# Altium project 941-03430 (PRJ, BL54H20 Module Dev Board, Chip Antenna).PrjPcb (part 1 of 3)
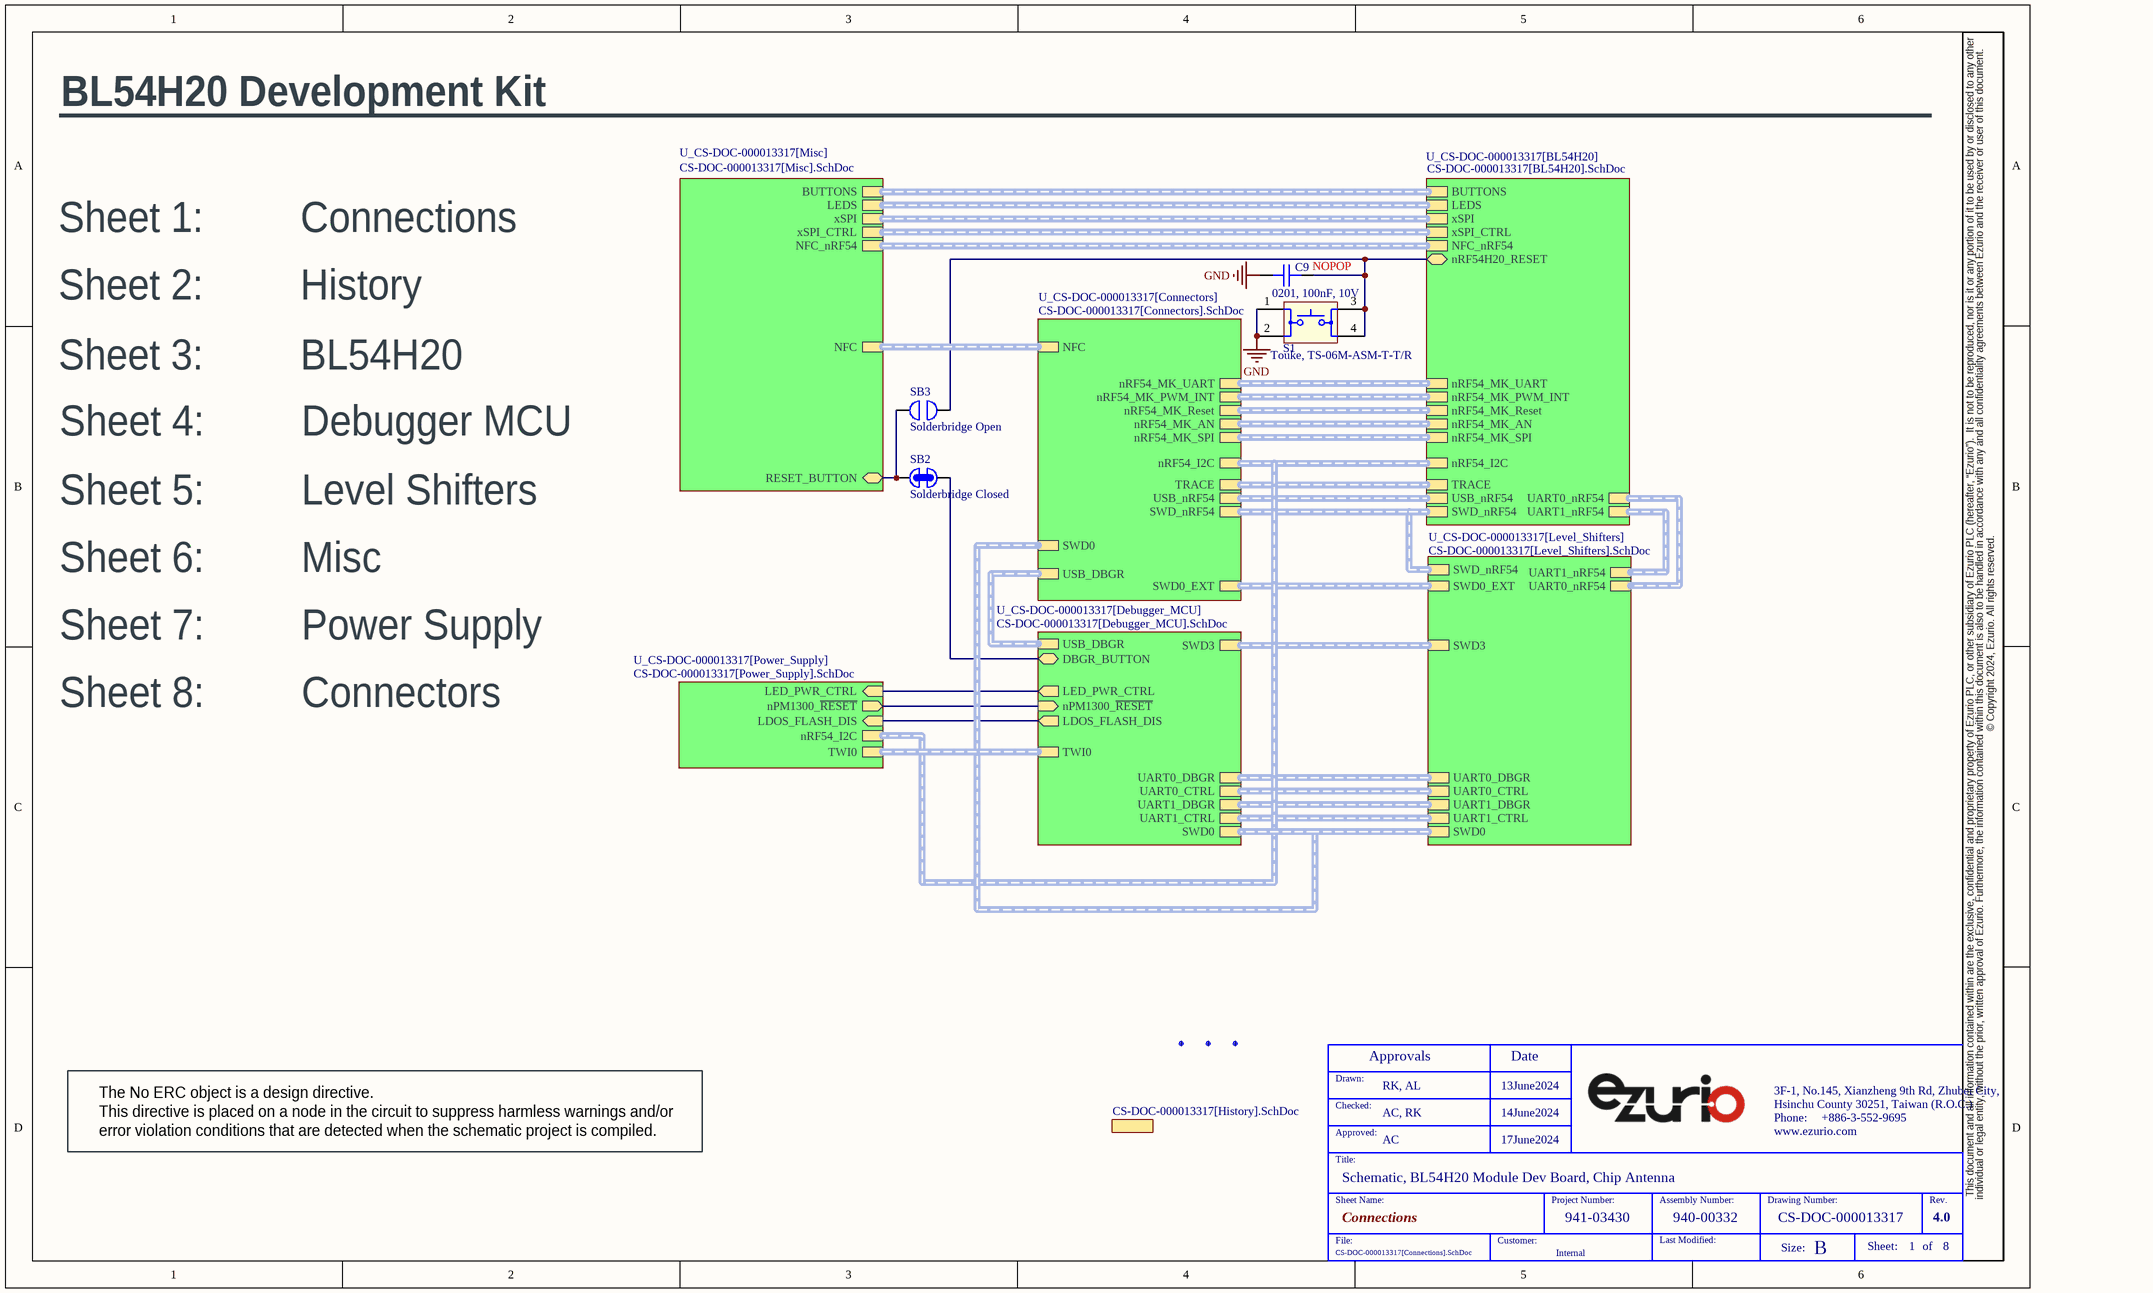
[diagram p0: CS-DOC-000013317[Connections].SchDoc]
ProjectWebsite: www.ezurio.com; ProjectVariantNumber: 940-00332; ProjectVariantDescription: Chip Antenna; ProjectTitle: BL54H20 Module Dev Board; ProjectSchematicRevision: 4.0; ProjectSchematicNumber: CS-DOC-000013317; ProjectRevision: 4.0; ProjectPhone: +886-3-552-9695; ProjectPCBRevision: 3.0; ProjectPCBNumber: 750-03430; ProjectNumber: 941-03430; ProjectDrawnDate: 13June2024; ProjectDrawnBy: RK, AL; ProjectCustomerName: Internal; ProjectCheckedDate: 14June2024; ProjectCheckedBy: AC, RK; ProjectBOMRevision: 4.0; ProjectBOMNumber: CS-DOC-000013318; ProjectAssyDocNumber: CS-DOC-000013316; ProjectApprovedDate: 17June2024; ProjectApprovedBy: AC; ProjectAddress3: Hsinchu County 30251, Taiwan (R.O.C.); ProjectAddress2: 3F-1, No.145, Xianzheng 9th Rd, Zhubei City,
8 sheets, 400 parts. Net scope: hierarchical (ports join the sheet entries above them; power ports are global).
Board file: 750-03430.PcbDoc
Sheets:
  CS-DOC-000013317[Connections].SchDoc
    CS-DOC-000013317[History] = CS-DOC-000013317[History].SchDoc
    U_CS-DOC-000013317[Connectors] = CS-DOC-000013317[Connectors].SchDoc
    U_CS-DOC-000013317[BL54H20] = CS-DOC-000013317[BL54H20].SchDoc
    U_CS-DOC-000013317[Debugger_MCU] = CS-DOC-000013317[Debugger_MCU].SchDoc
    U_CS-DOC-000013317[Level_Shifters] = CS-DOC-000013317[Level_Shifters].SchDoc
    U_CS-DOC-000013317[Misc] = CS-DOC-000013317[Misc].SchDoc
    U_CS-DOC-000013317[Power_Supply] = CS-DOC-000013317[Power_Supply].SchDoc

## Sheet CS-DOC-000013317[Connections].SchDoc: =BoardTitle +' Connections'
size B; Organization: Nordic Semiconductor; DocumentNumber: 1; SheetNumber: 1; SheetTotal: 8; CompanyName: Nordic Semiconductor; DocumentSize: A4; SheetName: Connections

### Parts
C9  0201, 100nF, 10V  [Cap, C0201, Height 0.3mm]
Fid1  Fiducial  [Fiducial]  (value not drawn)  (no BOM)
Fid2  Fiducial  [Fiducial]  (value not drawn)  (no BOM)
Fid3  Fiducial  [Fiducial]  (value not drawn)  (no BOM)
S1  Touke, TS-06M-ASM-T-T/R  [Touke, TS-06M-ASM-T]
SB2  Solderbridge Closed  [Solder Bridge Closed]  (net tie, no BOM)
SB3  Solderbridge Open  [Solder Bridge Open]  (no BOM)

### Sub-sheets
CS-DOC-000013317[History] = CS-DOC-000013317[History].SchDoc: no entries
U_CS-DOC-000013317[BL54H20] = CS-DOC-000013317[BL54H20].SchDoc: SWD_nRF54 (harness SWD), BUTTONS (harness UI), LEDS (harness UI), TRACE (harness TRACE), USB_nRF54 (harness USB_nRF), nRF54_I2C (harness I2C), nRF54_MK_UART (harness MIKROE UART), nRF54_MK_PWM_INT (harness MIKROE PWM INT), nRF54_MK_Reset (harness MIKROE Reset), nRF54_MK_AN (harness MIKROE Analog), nRF54_MK_SPI (harness MIKROE SPI), nRF54H20_RESET (bidir), xSPI (harness xSPI), NFC_nRF54 (harness NFC), UART0_nRF54 (harness UART), UART1_nRF54 (harness UART), xSPI_CTRL (harness xSPI_CTRL)
U_CS-DOC-000013317[Connectors] = CS-DOC-000013317[Connectors].SchDoc: SWD_nRF54 (harness SWD), TRACE (harness TRACE), NFC (harness NFC), SWD0_EXT (harness SWD), USB_nRF54 (harness USB_nRF), USB_DBGR (harness USB), nRF54_I2C (harness I2C), nRF54_MK_UART (harness MIKROE UART), nRF54_MK_PWM_INT (harness MIKROE PWM_INT), nRF54_MK_SPI (harness MIKROE SPI), nRF54_MK_AN (harness MIKROE Analog), nRF54_MK_Reset (harness MIKROE Reset), SWD0 (harness SWD)
U_CS-DOC-000013317[Debugger_MCU] = CS-DOC-000013317[Debugger_MCU].SchDoc: DBGR_BUTTON (bidir), SWD0 (harness SWD), UART0_DBGR (harness UART), USB_DBGR (harness USB), LED_PWR_CTRL (out), TWI0 (harness TWI), UART1_DBGR (harness UART), UART0_CTRL (harness UART CTRL), UART1_CTRL (harness UART CTRL), SWD3 (harness SWD), nPM1300_~{RESET} (in), LDOS_FLASH_DIS (out)
U_CS-DOC-000013317[Level_Shifters] = CS-DOC-000013317[Level_Shifters].SchDoc: SWD0 (harness SWD), UART0_DBGR (harness UART), SWD0_EXT (harness SWD), UART0_nRF54 (harness UART), UART1_nRF54 (harness UART), UART1_DBGR (harness UART), SWD_nRF54 (harness SWD), SWD3 (harness SWD), UART0_CTRL (harness UART CTRL), UART1_CTRL (harness UART CTRL)
U_CS-DOC-000013317[Misc] = CS-DOC-000013317[Misc].SchDoc: NFC_nRF54 (harness NFC), NFC (harness NFC), LEDS (harness UI), RESET_BUTTON (bidir), BUTTONS (harness UI), xSPI (harness xSPI), xSPI_CTRL (harness xSPI_CTRL)
U_CS-DOC-000013317[Power_Supply] = CS-DOC-000013317[Power_Supply].SchDoc: nRF54_I2C (harness I2C), LDOS_FLASH_DIS (in), nPM1300_~{RESET} (out), LED_PWR_CTRL (in), TWI0 (harness TWI)

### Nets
GND: C9.2 S1.1 S1.2
DBGR_BUTTON: SB2.2 ; sheet U_CS-DOC-000013317[Debugger_MCU]/DBGR_BUTTON
LDOS_FLASH_DIS: sheet U_CS-DOC-000013317[Debugger_MCU]/LDOS_FLASH_DIS, sheet U_CS-DOC-000013317[Power_Supply]/LDOS_FLASH_DIS
LED_PWR_CTRL: sheet U_CS-DOC-000013317[Debugger_MCU]/LED_PWR_CTRL, sheet U_CS-DOC-000013317[Power_Supply]/LED_PWR_CTRL
nPM1300_~{RESET}: sheet U_CS-DOC-000013317[Debugger_MCU]/nPM1300_~{RESET}, sheet U_CS-DOC-000013317[Power_Supply]/nPM1300_~{RESET}
nRF54H20_RESET: C9.1 S1.3 S1.4 SB3.2 ; sheet U_CS-DOC-000013317[BL54H20]/nRF54H20_RESET
RESET_BUTTON: SB2.1 SB3.1 ; sheet U_CS-DOC-000013317[Misc]/RESET_BUTTON

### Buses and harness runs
harness sheet U_CS-DOC-000013317[BL54H20]/BUTTONS = sheet U_CS-DOC-000013317[Misc]/BUTTONS
harness sheet U_CS-DOC-000013317[BL54H20]/LEDS = sheet U_CS-DOC-000013317[Misc]/LEDS
harness sheet U_CS-DOC-000013317[BL54H20]/NFC_nRF54 = sheet U_CS-DOC-000013317[Misc]/NFC_nRF54
harness sheet U_CS-DOC-000013317[BL54H20]/nRF54_I2C = sheet U_CS-DOC-000013317[Connectors]/nRF54_I2C = sheet U_CS-DOC-000013317[Power_Supply]/nRF54_I2C
harness sheet U_CS-DOC-000013317[BL54H20]/nRF54_MK_AN = sheet U_CS-DOC-000013317[Connectors]/nRF54_MK_AN
harness sheet U_CS-DOC-000013317[BL54H20]/nRF54_MK_PWM_INT = sheet U_CS-DOC-000013317[Connectors]/nRF54_MK_PWM_INT
harness sheet U_CS-DOC-000013317[BL54H20]/nRF54_MK_Reset = sheet U_CS-DOC-000013317[Connectors]/nRF54_MK_Reset
harness sheet U_CS-DOC-000013317[BL54H20]/nRF54_MK_SPI = sheet U_CS-DOC-000013317[Connectors]/nRF54_MK_SPI
harness sheet U_CS-DOC-000013317[BL54H20]/nRF54_MK_UART = sheet U_CS-DOC-000013317[Connectors]/nRF54_MK_UART
harness sheet U_CS-DOC-000013317[BL54H20]/SWD_nRF54 = sheet U_CS-DOC-000013317[Connectors]/SWD_nRF54 = sheet U_CS-DOC-000013317[Level_Shifters]/SWD_nRF54
harness sheet U_CS-DOC-000013317[BL54H20]/TRACE = sheet U_CS-DOC-000013317[Connectors]/TRACE
harness sheet U_CS-DOC-000013317[BL54H20]/UART0_nRF54 = sheet U_CS-DOC-000013317[Level_Shifters]/UART0_nRF54
harness sheet U_CS-DOC-000013317[BL54H20]/UART1_nRF54 = sheet U_CS-DOC-000013317[Level_Shifters]/UART1_nRF54
harness sheet U_CS-DOC-000013317[BL54H20]/USB_nRF54 = sheet U_CS-DOC-000013317[Connectors]/USB_nRF54
harness sheet U_CS-DOC-000013317[BL54H20]/xSPI = sheet U_CS-DOC-000013317[Misc]/xSPI
harness sheet U_CS-DOC-000013317[BL54H20]/xSPI_CTRL = sheet U_CS-DOC-000013317[Misc]/xSPI_CTRL
harness sheet U_CS-DOC-000013317[Connectors]/NFC = sheet U_CS-DOC-000013317[Misc]/NFC
harness sheet U_CS-DOC-000013317[Connectors]/SWD0 = sheet U_CS-DOC-000013317[Debugger_MCU]/SWD0 = sheet U_CS-DOC-000013317[Level_Shifters]/SWD0
harness sheet U_CS-DOC-000013317[Connectors]/SWD0_EXT = sheet U_CS-DOC-000013317[Level_Shifters]/SWD0_EXT
harness sheet U_CS-DOC-000013317[Connectors]/USB_DBGR = sheet U_CS-DOC-000013317[Debugger_MCU]/USB_DBGR
harness sheet U_CS-DOC-000013317[Debugger_MCU]/SWD3 = sheet U_CS-DOC-000013317[Level_Shifters]/SWD3
harness sheet U_CS-DOC-000013317[Debugger_MCU]/TWI0 = sheet U_CS-DOC-000013317[Power_Supply]/TWI0
harness sheet U_CS-DOC-000013317[Debugger_MCU]/UART0_CTRL = sheet U_CS-DOC-000013317[Level_Shifters]/UART0_CTRL
harness sheet U_CS-DOC-000013317[Debugger_MCU]/UART0_DBGR = sheet U_CS-DOC-000013317[Level_Shifters]/UART0_DBGR
harness sheet U_CS-DOC-000013317[Debugger_MCU]/UART1_CTRL = sheet U_CS-DOC-000013317[Level_Shifters]/UART1_CTRL
harness sheet U_CS-DOC-000013317[Debugger_MCU]/UART1_DBGR = sheet U_CS-DOC-000013317[Level_Shifters]/UART1_DBGR

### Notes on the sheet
- ________________________________________________________________
- BL54H20 Development Kit
- Sheet 1:         Connections
- (near C9) NOPOP
- Sheet 2:         History
- Sheet 3:         BL54H20
- Sheet 4:         Debugger MCU
- Sheet 5:         Level Shifters
- Sheet 6:         Misc
- Sheet 7:         Power Supply
- Sheet 8:         Connectors
- The No ERC object is a design directive.
  This directive is placed on a node in the circuit to suppress harmless warnings and/or error violation conditions that are detected when the schematic project is compiled.

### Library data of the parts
C9 = CMP-CAP-502-00106-1.11: CAP, SMT, 0201, MLCC, 100nF, 10V, X7S, 10%; Manufacturer: Murata; Manufacturer Part Number: GRM033C71A104KE14#; Substitutes Allowed: NO
Fid1-Fid3 = CMP-MSC-SMT-WTS-522-0002-1.8: Fiducial Mark; Substitutes Allowed: NO
S1 = CMP-SW-516-00005-1.12: SW, SMT, Tact, Vertical, Momentary On, 6mm x 6mm x 4.3mm; Substitutes Allowed: NO; Voltage Rating AC/DC: 500VAC-1 minute; Switch Circuit: SPST; Switch Function: (On, Off, Mom)
SB2 = CMP-Misc-522-00004-1.17: MSC, Solderbridge Closed
SB3 = CMP-Misc-522-00003-1.9: MSC, Solderbridge Open

## Sheet CS-DOC-000013317[History].SchDoc
size B; SheetNumber: 2; SheetTotal: 8; SheetName: History
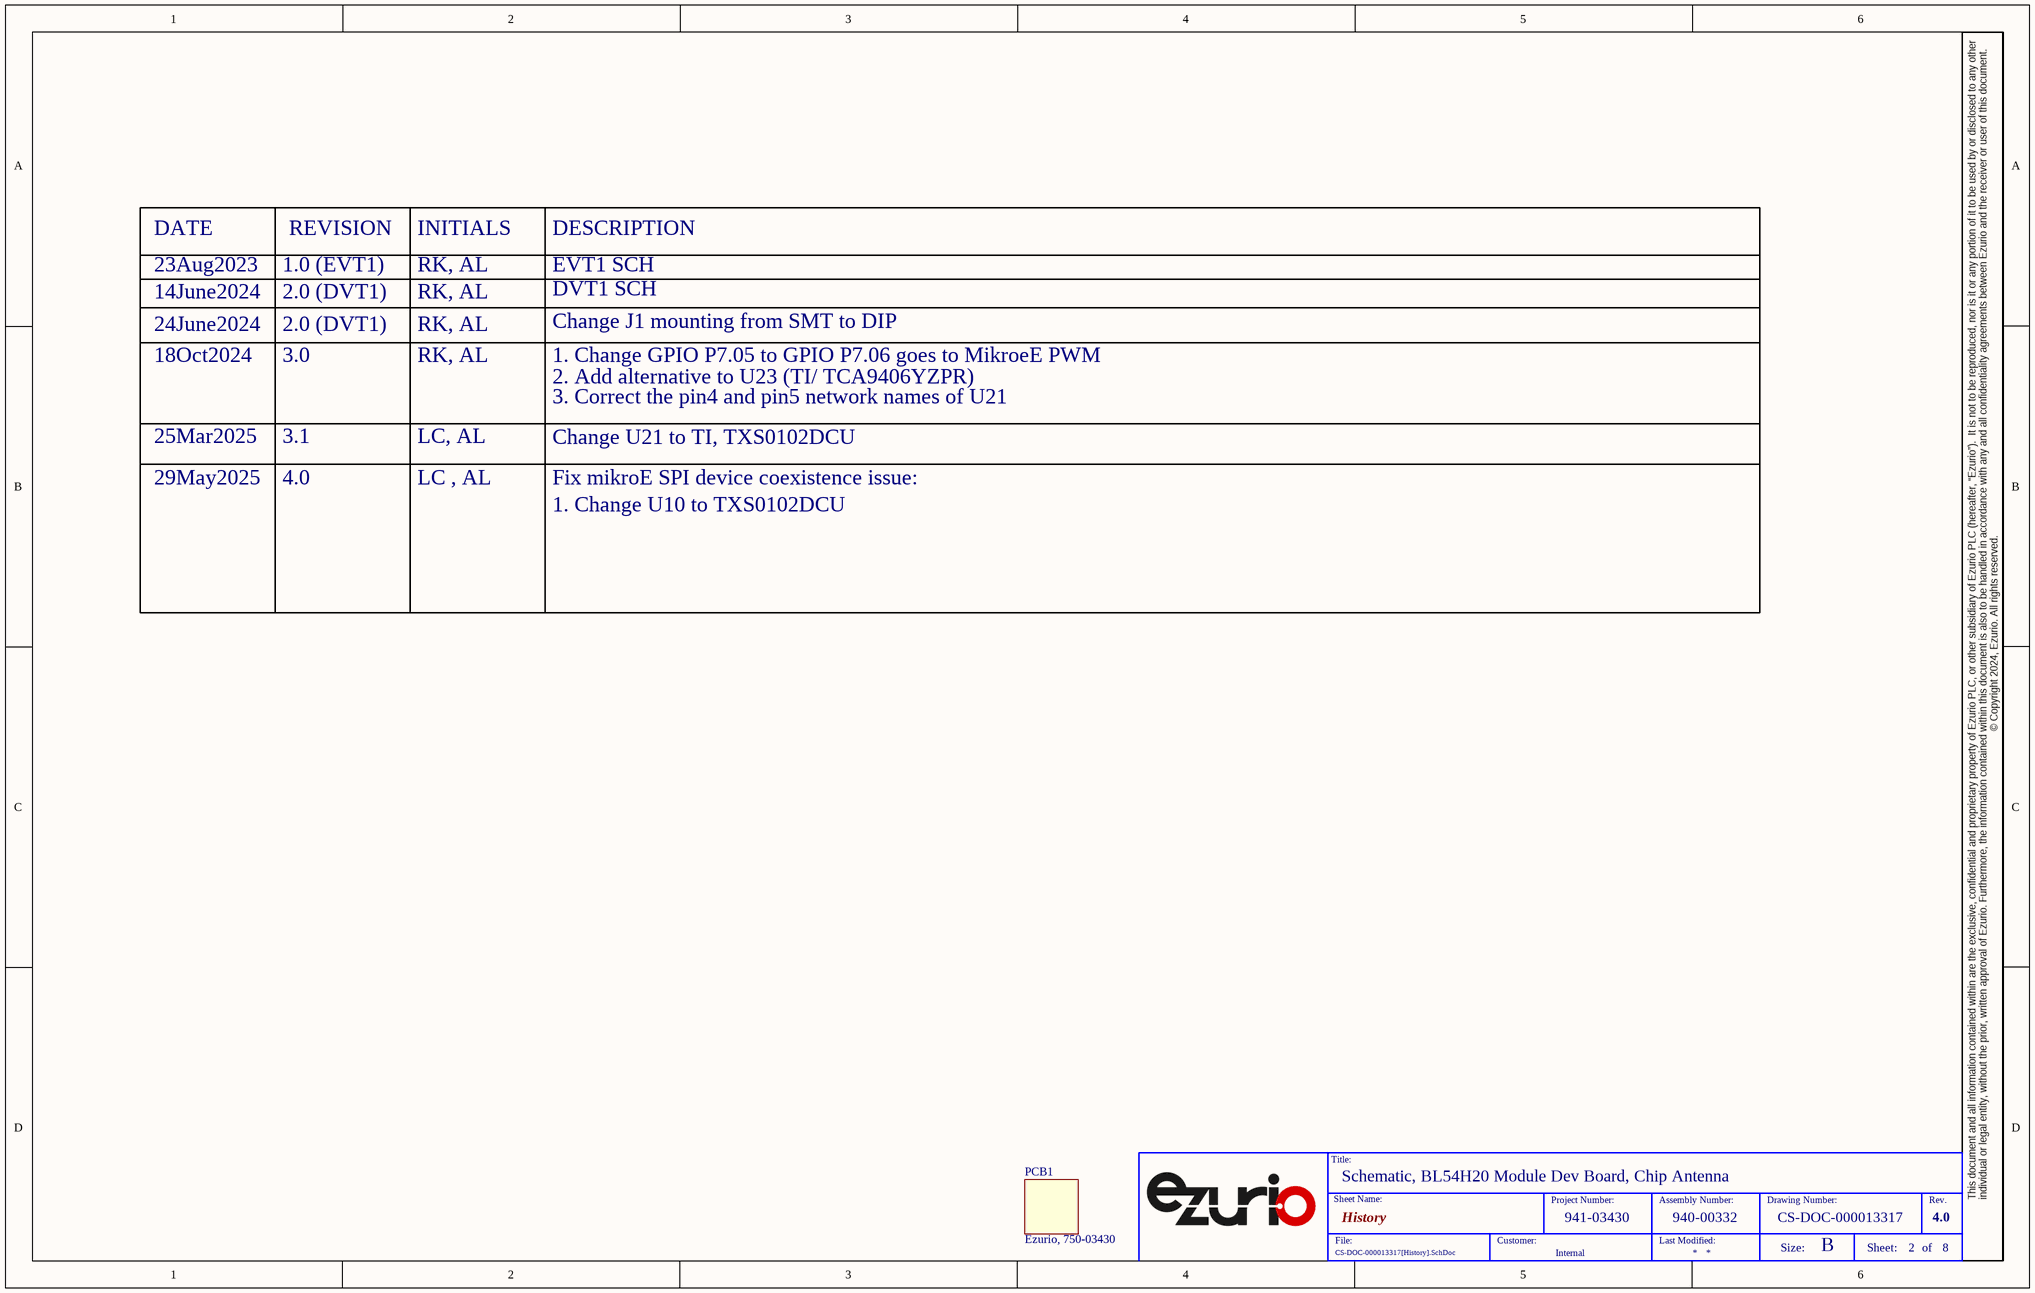
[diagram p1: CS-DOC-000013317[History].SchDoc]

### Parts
PCB1  Ezurio, 750-03430  [Laird, Logo, Silkscreen, TW]  (mechanical)

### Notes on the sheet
- DATE
- REVISION
- INITIALS
- DESCRIPTION
- 23Aug2023
- 14June2024
- 1.0 (EVT1)
- 2.0 (DVT1)
- RK, AL
- EVT1 SCH
- DVT1 SCH
- 24June2024
- 18Oct2024
- 3.0
- Change J1 mounting from SMT to DIP
- 1. Change GPIO P7.05 to GPIO P7.06 goes to MikroeE PWM
- 2. Add alternative to U23 (TI/ TCA9406YZPR)
- 3. Correct the pin4 and pin5 network names of U21
- 25Mar2025
- 29May2025
- 3.1
- 4.0
- LC, AL
- LC , AL
- Change U21 to TI, TXS0102DCU
- Fix mikroE SPI device coexistence issue:
- 1. Change U10 to TXS0102DCU

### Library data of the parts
PCB1 = CMP-PCB-750-00054-1.1: PCB, BL54H20 Module Dev Board, Chip Antenna; Substitutes Allowed: NO

## Sheet CS-DOC-000013317[Connectors].SchDoc: =BoardTitle +' Connectors'
size OrCAD C; Organization: Nordic Semiconductor; DocumentNumber: 8; SheetNumber: 8; SheetTotal: 8; CompanyName: Nordic Semiconductor; DocumentSize: A4; SheetName: Connectors
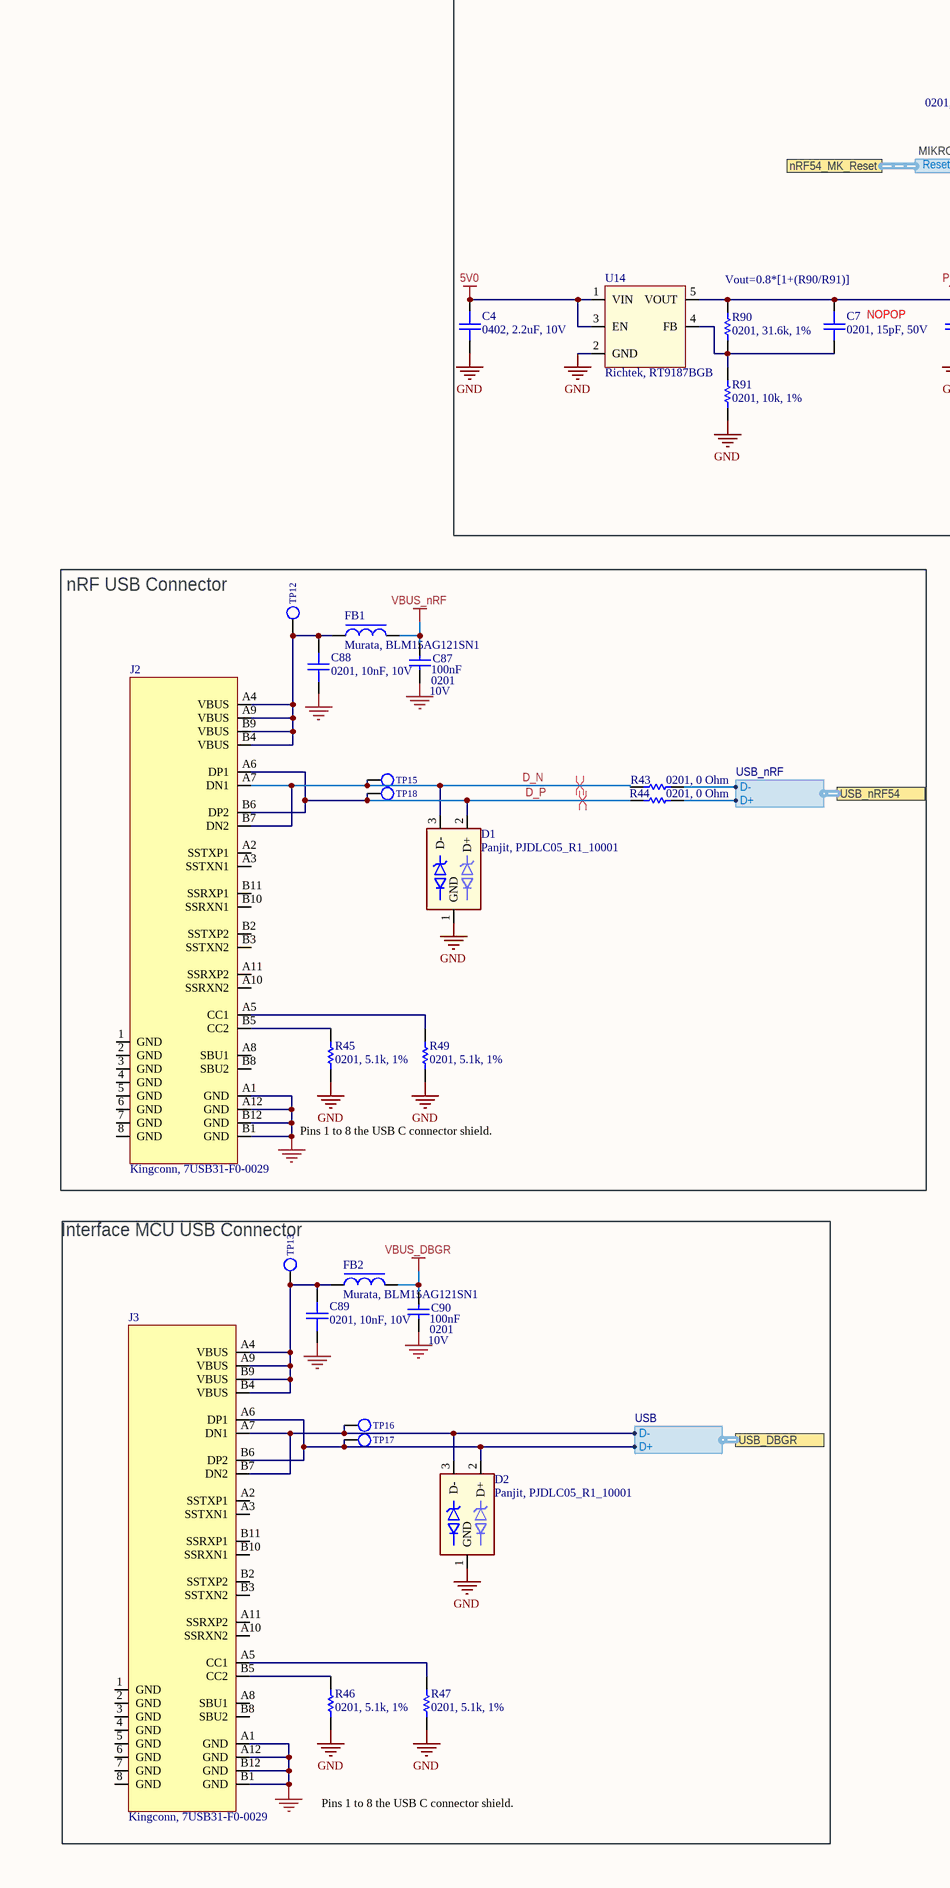
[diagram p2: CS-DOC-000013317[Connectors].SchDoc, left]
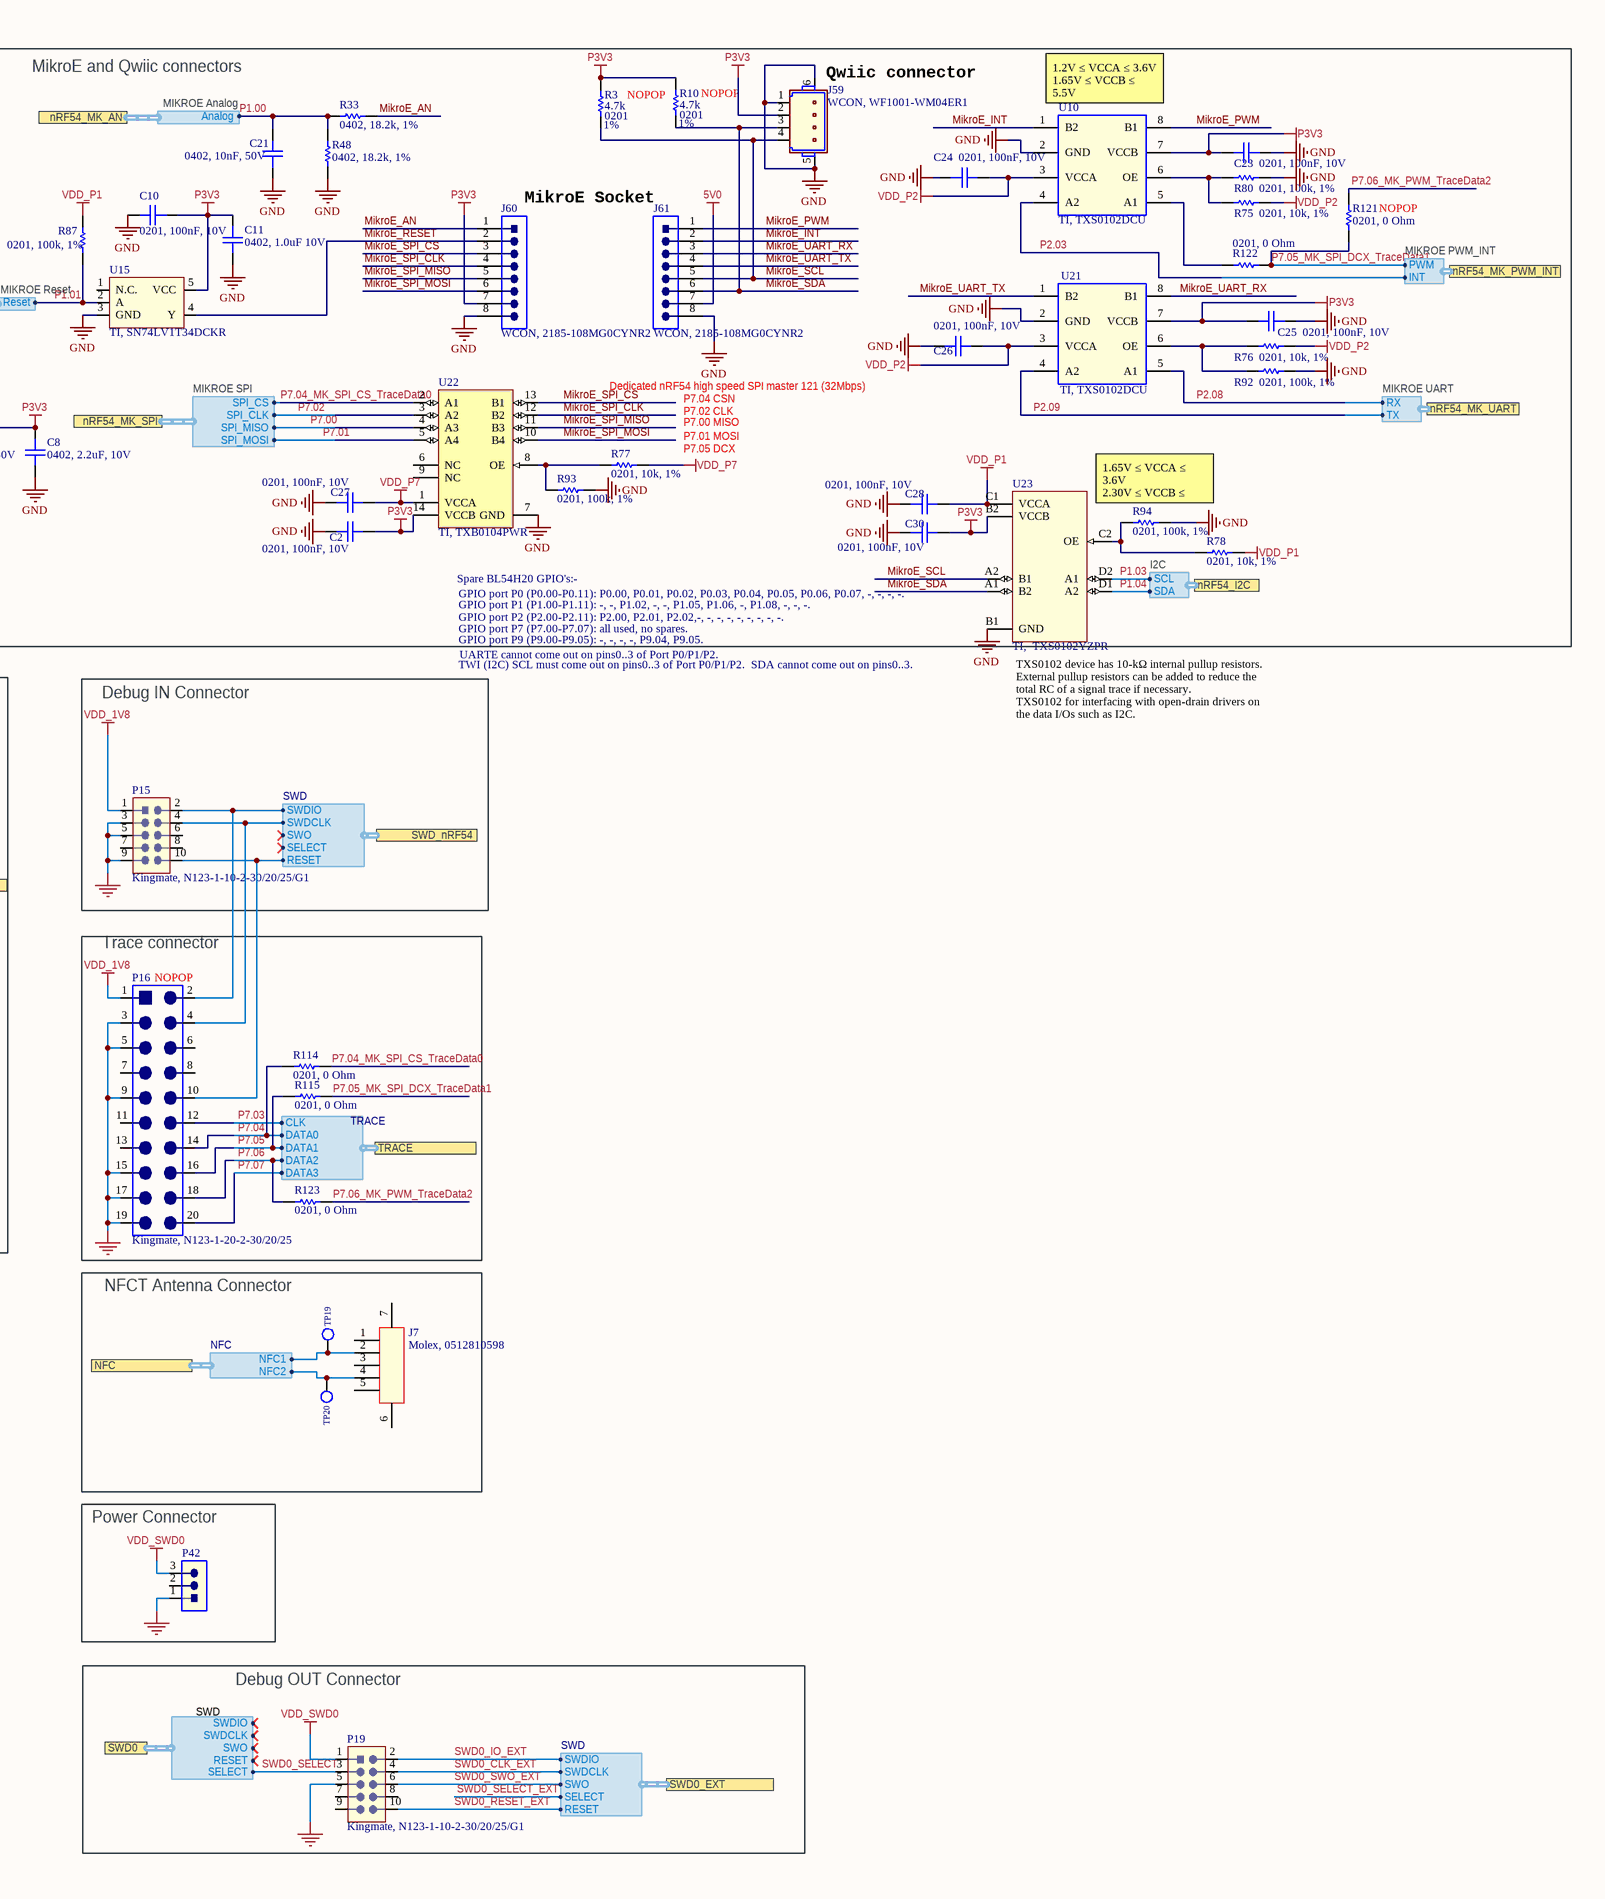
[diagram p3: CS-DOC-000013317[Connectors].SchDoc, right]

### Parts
C2  0201, 100nF, 10V  [Cap, C0201, Height 0.3mm]
C4  0402, 2.2uF, 10V  [Chip. 0402, RF]
C7  0201, 15pF, 50V  [Cap, C0201, Height 0.3mm]
C8  0402, 2.2uF, 10V  [Chip. 0402, RF]
C10  0201, 100nF, 10V  [Cap, C0201, Height 0.3mm]
C11  0402, 1.0uF 10V  [Chip. 0402, RF]
C21  0402, 10nF, 50V  [Chip. 0402, RF]
C23  0201, 100nF, 10V  [Cap, C0201, Height 0.3mm]
C24  0201, 100nF, 10V  [Cap, C0201, Height 0.3mm]
C25  0201, 100nF, 10V  [Cap, C0201, Height 0.3mm]
C26  0201, 100nF, 10V  [Cap, C0201, Height 0.3mm]
C27  0201, 100nF, 10V  [Cap, C0201, Height 0.3mm]
C28  0201, 100nF, 10V  [Cap, C0201, Height 0.3mm]
C30  0201, 100nF, 10V  [Cap, C0201, Height 0.3mm]
C87  value 100nF  Footprint: 0201  Voltage: 10V  [Cap, C0201, Height 0.3mm]  (hidden comment: 0201, 100nF, 10V)
C88  0201, 10nF, 10V  [Cap, C0201, Height 0.3mm]
C89  0201, 10nF, 10V  [Cap, C0201, Height 0.3mm]
C90  value 100nF  Footprint: 0201  Voltage: 10V  [Cap, C0201, Height 0.3mm]  (hidden comment: 0201, 100nF, 10V)
D1  Panjit, PJDLC05_R1_10001  [SOT-23]
D2  Panjit, PJDLC05_R1_10001  [SOT-23]
FB1  Murata, BLM15AG121SN1  [FB, FB0402, RF]
FB2  Murata, BLM15AG121SN1  [FB, FB0402, RF]
J2  Kingconn, 7USB31-F0-0029  [Kingconn, 7USB31-F0-0029]
J3  Kingconn, 7USB31-F0-0029  [Kingconn, 7USB31-F0-0029]
J7  Molex, 0512810598  [Molex, 0512810598]
J59  WCON, WF1001-WM04ER1  [CON WAFER, 1X4P]
J60  WCON, 2185-108MG0CYNR2  [2P54MM-1X8, Female]
J61  WCON, 2185-108MG0CYNR2  [2P54MM-1X8, Female]
P15  Kingmate, N123-1-10-2-30/20/25/G1  [1P27MM-2X5 Male]
P16  Kingmate, N123-1-20-2-30/20/25  [1P27MM-2X10 Male]
P19  Kingmate, N123-1-10-2-30/20/25/G1  [1P27MM-2X5 Male]
P42  Kingmate, S113-A-03-2-60/33-F0  [2P54MM-1X3, male]  (value not drawn)
R3  value 4.7k  Tolerance: 1%  Footprint: 0201  [RES, R0201, Height 0.23mm]  (hidden comment: 0201, 4.7k, 1%)
R10  value 4.7k  Tolerance: 1%  Footprint: 0201  [RES, R0201, Height 0.23mm]  (hidden comment: 0201, 4.7k, 1%)
R33  0402, 18.2k, 1%  [RES, R0402, RF]
R43  0201, 0 Ohm  [RES, R0201, Height 0.23mm]
R44  0201, 0 Ohm  [RES, R0201, Height 0.23mm]
R45  0201, 5.1k, 1%  [RES, R0201, Height 0.23mm]
R46  0201, 5.1k, 1%  [RES, R0201, Height 0.23mm]
R47  0201, 5.1k, 1%  [RES, R0201, Height 0.23mm]
R48  0402, 18.2k, 1%  [RES, R0402, RF]
R49  0201, 5.1k, 1%  [RES, R0201, Height 0.23mm]
R75  0201, 10k, 1%  [RES, R0201, Height 0.23mm]
R76  0201, 10k, 1%  [RES, R0201, Height 0.23mm]
R77  0201, 10k, 1%  [RES, R0201, Height 0.23mm]
R78  0201, 10k, 1%  [RES, R0201, Height 0.23mm]
R80  0201, 100k, 1%  [RES, R0201, Height 0.23mm]
R87  0201, 100k, 1%  [RES, R0201, Height 0.23mm]
R90  0201, 31.6k, 1%  [RES, R0201, Height 0.23mm]
R91  0201, 10k, 1%  [RES, R0201, Height 0.23mm]
R92  0201, 100k, 1%  [RES, R0201, Height 0.23mm]
R93  0201, 100k, 1%  [RES, R0201, Height 0.23mm]
R94  0201, 100k, 1%  [RES, R0201, Height 0.23mm]
R114  0201, 0 Ohm  [RES, R0201, Height 0.23mm]
R115  0201, 0 Ohm  [RES, R0201, Height 0.23mm]
R121  0201, 0 Ohm  [RES, R0201, Height 0.23mm]
R122  0201, 0 Ohm  [RES, R0201, Height 0.23mm]
R123  0201, 0 Ohm  [RES, R0201, Height 0.23mm]
TP12  SMT, 1.5mm, Test Pad  [Test Point, SMT 1.5mm Round]  (value not drawn)  (no BOM)
TP13  SMT, 1.5mm, Test Pad  [Test Point, SMT 1.5mm Round]  (value not drawn)  (no BOM)
TP15  SMT, 1.5mm, Test Pad  [Test Point, SMT 1.5mm Round]  (value not drawn)  (no BOM)
TP16  SMT, 1.5mm, Test Pad  [Test Point, SMT 1.5mm Round]  (value not drawn)  (no BOM)
TP17  SMT, 1.5mm, Test Pad  [Test Point, SMT 1.5mm Round]  (value not drawn)  (no BOM)
TP18  SMT, 1.5mm, Test Pad  [Test Point, SMT 1.5mm Round]  (value not drawn)  (no BOM)
TP19  SMT, 1.5mm, Test Pad  [Test Point, SMT 1.5mm Round]  (value not drawn)  (no BOM)
TP20  SMT, 1.5mm, Test Pad  [Test Point, SMT 1.5mm Round]  (value not drawn)  (no BOM)
U10  TI, TXS0102DCU  [VFSOP8_2x2.3]
U14  Richtek, RT9187BGB  [SOT23-5, Height1.3mm]
U15  TI, SN74LV1T34DCKR  [SC70-5]
U21  TI, TXS0102DCU  [VFSOP8_2x2.3]
U22  TI, TXB0104PWR  [SOP-14, Body 5.1x4.5mm, Pitch 0.65mm, IPC High Density]
U23  TI,  TXS0102YZPR  [TI, TXS0102YZPR]

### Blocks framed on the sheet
MikroE and Qwiic connectors: C2 C4 C7 C8 C10 C11 C21 C23-C28 C30 J59-J61 R3 R10 R33 R48 R75-R78 R80 R87 R90-R94 R121 R122 U10 U14 U15 U21-U23
nRF USB Connector: C87 C88 D1 FB1 J2 R43-R45 R49 TP12 TP15 TP18
Debug IN Connector: P15
Trace connector: P16 R114 R115 R123
Interface MCU USB Connector: C89 C90 D2 FB2 J3 R46 R47 TP13 TP16 TP17
NFCT Antenna Connector: J7 TP19 TP20
Power Connector: P42
Debug OUT Connector: P19

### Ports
NFC (harness NFC), nRF54_I2C (harness I2C), nRF54_MK_AN (harness MIKROE Analog), nRF54_MK_PWM_INT (harness MIKROE PWM_INT), nRF54_MK_Reset (harness MIKROE Reset), nRF54_MK_SPI (harness MIKROE SPI), nRF54_MK_UART (harness MIKROE UART), SWD0 (harness SWD), SWD0_EXT (harness SWD), SWD_nRF54 (harness SWD), TRACE (harness TRACE), USB_DBGR (harness USB), USB_nRF54 (harness USB_nRF)

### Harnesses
USB_nRF: D+, D-
SWD: SWDIO, SWDCLK, SWO, RESET, SELECT
TRACE: CLK, DATA0, DATA1, DATA3, DATA2
NFC: NFC2, NFC1
I2C: SCL, SDA
MIKROE UART: TX, RX
MIKROE PWM_INT: PWM, INT
MIKROE SPI: SPI_MISO, SPI_MOSI, SPI_CLK, SPI_CS
MIKROE Analog: Analog
MIKROE Reset: Reset
USB: D+, D-

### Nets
5V0: C4.1 J61.7 U14.1(VIN) U14.3(EN)
GND: C2.1 C4.2 C8.2 C10.2 C11.2 C21.1 C23.1 C24.1 C25.1 C26.1 C27.1 C28.1 C30.1 C87.2 C88.1 C89.1 C90.2 D1.1(GND) D2.1(GND) J2.A1(GND) J2.A12(GND) J2.B1(GND) J2.B12(GND) J3.A1(GND) J3.A12(GND) J3.B1(GND) J3.B12(GND) J59.1 J59.5(GND) J59.6(GND2) J60.8 J61.8 P15.3 P15.5 P15.9 P16.3 P16.5 P16.9 P16.15 P16.17 P16.19 P19.5 P42.1 R45.1 R46.1 R47.2 R48.1 R49.1 R80.2 R91.2 R92.2 R93.2 R94.2 U10.2(GND) U14.2(GND) U15.3(GND) U21.2(GND) U22.7(GND) U23.B1(GND)
P3V3: C2.2 C7.1 C8.1 C10.1 C11.1 C23.2 C25.2 C30.2 J59.2 J60.7 R3.2 R10.2 R90.1 U10.7(VCCB) U14.5(VOUT) U15.5(VCC) U21.7(VCCB) U22.14(VCCB) U23.B2(VCCB)
VBUS_DBGR: C90.1 FB2.2
VBUS_nRF: C87.1 FB1.2
VDD_1V8: P15.1 P16.1
VDD_P1: C28.2 R78.2 R87.1 U23.C1(VCCA)
VDD_P2: C24.2 C26.2 R75.2 R76.2 U10.3(VCCA) U21.3(VCCA)
VDD_P7: C27.2 R77.2 U22.1(VCCA)
VDD_SWD0: P19.1 P42.3
D_N: D1.3(D-) J2.A7(DN1) J2.B7(DN2) R43.2 TP15.1
D_P: D1.2(D+) J2.A6(DP1) J2.B6(DP2) R44.2 TP18.1
DBGR_N: D2.3(D-) J3.A7(DN1) J3.B7(DN2) TP16.1 ; port USB_DBGR.D-
DBGR_P: D2.2(D+) J3.A6(DP1) J3.B6(DP2) TP17.1 ; port USB_DBGR.D+
MikroE_AN: J60.1 R33.2
MikroE_INT: J61.2 U10.1(B2)
MikroE_PWM: J61.1 U10.8(B1)
MikroE_RESET: J60.2 U15.4(Y)
MikroE_SCL: J59.4 J61.5 R3.1 U23.A2(B1)
MikroE_SDA: J59.3 J61.6 R10.1 U23.A1(B2)
MikroE_SPI_CLK: J60.4 U22.12(B2)
MikroE_SPI_CS: J60.3 U22.13(B1)
MikroE_SPI_MISO: J60.5 U22.11(B3)
MikroE_SPI_MOSI: J60.6 U22.10(B4)
MikroE_UART_RX: J61.3 U21.8(B1)
MikroE_UART_TX: J61.4 U21.1(B2)
NFC1: J7.2 TP19.1 ; port NFC.NFC1
NFC2: J7.4 TP20.1 ; port NFC.NFC2
nRF54_N: R43.1 ; port USB_nRF54.D-
nRF54_P: R44.1 ; port USB_nRF54.D+
nRF54H20_RESET: P15.10 P16.10 ; port SWD_nRF54.RESET
P1.00: C21.2 R33.1 R48.2 ; port nRF54_MK_AN.Analog
P1.01: R87.2 U15.2(A) ; port nRF54_MK_Reset.Reset
P1.03: U23.D2(A1) ; port nRF54_I2C.SCL
P1.04: U23.D1(A2) ; port nRF54_I2C.SDA
P2.03: U10.4(A2) ; port nRF54_MK_PWM_INT.INT
P2.08: U21.5(A1) ; port nRF54_MK_UART.RX
P2.09: U21.4(A2) ; port nRF54_MK_UART.TX
P7.00: U22.4(A3) ; port nRF54_MK_SPI.SPI_MISO
P7.01: U22.5(A4) ; port nRF54_MK_SPI.SPI_MOSI
P7.02: U22.3(A2) ; port nRF54_MK_SPI.SPI_CLK
P7.03: P16.12 ; port TRACE.CLK
P7.04: P16.14 R114.2 ; port TRACE.DATA0
P7.04_MK_SPI_CS_TraceData0: R114.1 U22.2(A1) ; port nRF54_MK_SPI.SPI_CS
P7.05: P16.16 R115.2 ; port TRACE.DATA1
P7.05_MK_SPI_DCX_TraceData1: R115.1 R121.2 R122.1 ; port nRF54_MK_PWM_INT.PWM
P7.06: P16.18 R123.2 ; port TRACE.DATA2
P7.06_MK_PWM_TraceData2: R121.1 R123.1
P7.07: P16.20 ; port TRACE.DATA3
SWD0_CLK_EXT: P19.4 ; port SWD0_EXT.SWDCLK
SWD0_IO_EXT: P19.2 ; port SWD0_EXT.SWDIO
SWD0_RESET_EXT: P19.10 ; port SWD0_EXT.RESET
SWD0_SELECT: P19.3 ; port SWD0.SELECT
SWD0_SWO_EXT: P19.6 ; port SWD0_EXT.SWO
SWDCLK: P15.4 P16.4 ; port SWD_nRF54.SWDCLK
SWDIO: P15.2 P16.2 ; port SWD_nRF54.SWDIO
NetC7_2: C7.2 R90.2 R91.1 U14.4(FB)
NetC88_2: C88.2 FB1.1 J2.A4(VBUS) J2.A9(VBUS) J2.B4(VBUS) J2.B9(VBUS) TP12.1
NetC89_2: C89.2 FB2.1 J3.A4(VBUS) J3.A9(VBUS) J3.B4(VBUS) J3.B9(VBUS) TP13.1
NetJ2_A5: J2.A5(CC1) R49.2
NetJ2_B5: J2.B5(CC2) R45.2
NetJ3_A5: J3.A5(CC1) R47.1
NetJ3_B5: J3.B5(CC2) R46.2
NetR75_1: R75.1 R80.1 U10.6(OE)
NetR76_1: R76.1 R92.1 U21.6(OE)
NetR77_1: R77.1 R93.1 U22.8(OE)
NetR78_1: R78.1 R94.1 U23.C2(OE)
NetR122_2: R122.2 U10.5(A1)

Not connected (* = marked no-connect by the designer): J2 1(GND) 2(GND) 3(GND) 4(GND) 5(GND) 6(GND) 7(GND) 8(GND) A2(SSTXP1) A3(SSTXN1) A8(SBU1) A10(SSRXN2) A11(SSRXP2) B2(SSTXP2) B3(SSTXN2) B8(SBU2) B10(SSRXN1) B11(SSRXP1); J3 1(GND) 2(GND) 3(GND) 4(GND) 5(GND) 6(GND) 7(GND) 8(GND) A2(SSTXP1) A3(SSTXN1) A8(SBU1) A10(SSRXN2) A11(SSRXP2) B2(SSTXP2) B3(SSTXN2) B8(SBU2) B10(SSRXN1) B11(SSRXP1); J7 1 3 5 6 7; P15 6 7 8; P16 6 7 8 11 13; P19 7 8 9; P42 2; U15 1(N.C.); U22 6(NC) 9(NC)

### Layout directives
differential pair; differential pair class USB_CONN; net class USB: D_N, D_P

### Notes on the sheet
- (near J59) Qwiic connector
- NOPOP
- (near R10) NOPOP
- (near U10) 1.2V ≤ VCCA ≤ 3.6V
  1.65V ≤ VCCB ≤ 5.5V
  & VCCA ≤VCCB
- MikroE Socket
- (near R121) NOPOP
- Dedicated nRF54 high speed SPI master 121 (32Mbps)
- Vout=0.8*[1+(R90/R91)]
- (near C7) NOPOP
- P7.00 MISO
- P7.01 MOSI
- P7.02 CLK
- P7.04 CSN
- (near R77) P7.05 DCX
- (near U23) 1.65V ≤ VCCA ≤ 3.6V
  2.30V ≤ VCCB ≤ 5.5V
  & VCCA ≤VCCB
- Spare BL54H20 GPIO's:-
- GPIO port P7 (P7.00-P7.07): all used, no spares.
- (near U23) GPIO port P0 (P0.00-P0.11): P0.00, P0.01, P0.02, P0.03, P0.04, P0.05, P0.06, P0.07, -, -, -, -.
- GPIO port P1 (P1.00-P1.11): -, -, P1.02, -, -, P1.05, P1.06, -, P1.08, -, -, -.
- GPIO port P2 (P2.00-P2.11): P2.00, P2.01, P2.02,-, -, -, -, -, -, -, -, -.
- GPIO port P9 (P9.00-P9.05): -, -, -, -, P9.04, P9.05.
- TWI (I2C) SCL must come out on pins0..3 of Port P0/P1/P2.  SDA cannot come out on pins0..3.
- UARTE cannot come out on pins0..3 of Port P0/P1/P2.
- (near U23) TXS0102 device has 10-kΩ internal pullup resistors. External pullup resistors can be added to reduce the total RC of a signal trace if necessary.
  TXS0102 for interfacing with open-drain drivers on the data I/Os such as I2C.
- (near P16) NOPOP
- Pins 1 to 8 the USB C connector shield.

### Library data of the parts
C2 C10 C23-C28 C30 = CMP-CAP-502-00106-1.11: as C9 on sheet CS-DOC-000013317[Connections]
C4 C8 = CMP-CAP-502-00198-1.11: CAP, SMT, 0402, MLCC, 2.2uF, 10V, X7S, 10%; Manufacturer: Murata; Manufacturer Part Number: GRM155C71A225KE11#; Substitutes Allowed: NO
C7 = CMP-CAP-502-00072-1.19: CAP, SMT, 0201, MLCC, 15pF, 50V, C0G, 5%; Manufacturer Part Number: CC0201JRNPO9BN150; Alt. Manufacturer: MURATA; Manufacturer: Yageo; Alt. Manufacturer Part Number: GRM0335C1H150JA01#; Substitutes Allowed: YES
C11 = CMP-CAP-502-00101-1.17: CAP, SMT, 0402, MLCC, 1.0uF, 10V, X7S, 10%; Manufacturer: Murata; Manufacturer Part Number: GRM155C71A105KE11#; Substitutes Allowed: NO
C21 = CMP-CAP-502-00063-1.16: CAP, SMT, 0402, MLCC, 10nF, 50V, X7R, 10%; Manufacturer Part Number: CC0402KRX7R9BB103; Manufacturer: Yageo; Substitutes Allowed: NO
C87 C90 = CMP-CAP-502-00106-1.11: CAP, SMT, 0201, MLCC, 100nF, 10V, X7S, 10%; Manufacturer Part Number: GRM033C71A104KE14#; Manufacturer: Murata; Substitutes Allowed: NO
C88 C89 = CMP-CAP-502-00031-1.14: CAP, SMT, 0201, MLCC, 10nF, 10V, X7R, 10%; Manufacturer: Walsin; Alt. Manufacturer: Murata; Manufacturer Part Number: 0201B103K100CT; Alt. Manufacturer Part Number: GRM033R71A103K; Substitutes Allowed: YES
D1 D2 = CMP-IC-510-00074-1.2: IC, SMT, SOT23, Overvoltage-Suppressor,5V,400W,ESD-15KV-Air, 8KV-Contact, 3.3V~24V, 400W; Substitutes Allowed: NO
FB1 FB2 = CMP-FB-505-00005-1.3: FB, SMT, 0402, 120 Ohm @ 100MHz, 450mA, 190 mOhm,; Substitutes Allowed: NO; Current: 550mA
J2 J3 = CMP-CON-130-00120-1.4: CON, TH, USB-C Type, 24 PIN, DIP+SMT 90d; Substitutes Allowed: NO; Rows: NA; Pin Pitch: 0.5mm
J7 = CMP-CON-130-00213-1.1: CON, SMT,Custom, FPC,1x5,1.20mm, NFC Connector; Subpart Type: FFC; Pin Pitch: 0.5mm; Rows: 1; Substitutes Allowed: NO
J59 = CMP-CON-130-00167-1.4: CON, SMT, Wafer, 1x4, Pitch 1.0mm, Vertical; Subpart Type: WIRE TO BOARD WAFER; Substitutes Allowed: NO; Rows: 1; Voltage: 100V
J60 J61 = CMP-CON-130-00168-1.2: CON, SMT, Female Header, 2P54MM-1X8, Pitch 2.54mm, PHY 0.64mm; Alt. Manufacturer: Kingmate; Alt. Manufacturer Part Number: S214-B-08-2-89-F1; Substitutes Allowed: YES; Rows: 1
P15 P19 = CMP-CON-130-00112-1.1: CON, SMT, Header, 2x5, Pitch 1.27mm, Vertical; Rows: 2; Substitutes Allowed: NO
P16 = CMP-CON-130-00048-1.7: CON, SMT, Header, 2x10 pin, 1.27mm pitch, Male,; Voltage: 1000V; Substitutes Allowed: NO; Rows: 2
P42 = CMP-CON-130-00220-1.3: CON, SMT, Header, 1X3 pins, 2.54mm pitch, Male, Vertical; Rows: 1; Substitutes Allowed: NO
R3 R10 = CMP-RES-514-00018-1.29: RES, SMT, 0201, Thick Film, 4.7k, 1%, 0.05W; Manufacturer: Yageo; Alt. Manufacturer: Any; Manufacturer Part Number: RC0201FR-074K7L; Substitutes Allowed: YES
R33 R48 = CMP-RES-514-00333-1.2: RES, SMT, 0402, Thick Film, 18.2k, 1%, 0.0625W; Alt. Manufacturer Part Number: Any; Manufacturer Part Number: RC0402FR-0718K2L; Manufacturer: Yageo; Substitutes Allowed: YES
R43 R44 = CMP-RES-514-00004-1.31: RES, SMT, 0201, Thick Film, 0, 0.05W; Manufacturer: Yageo; Alt. Manufacturer: Any; Manufacturer Part Number: RC0201JR-070RL; Tolerance: NA; Substitutes Allowed: YES; Value: 0
R45-R47 R49 = CMP-RES-514-00342-1.0: RES, SMT, 0201, Thick Film, 5.1k, 1%, 0.05W; Manufacturer: Yageo; Alt. Manufacturer Part Number: Any; Manufacturer Part Number: RC0201FR-075K1L; Substitutes Allowed: YES
R75-R78 R91 = CMP-RES-514-00247-1.2: RES, SMT, 0201, Thick Film, 10k, 1%, 0.05W; Alt. Manufacturer Part Number: Any; Manufacturer Part Number: RC0201FR-7D10KL; Manufacturer: Yageo; Substitutes Allowed: YES
R80 R87 R92-R94 = CMP-RES-514-00064-1.24: RES, SMT, 0201, Thick Film, 100k, 1%, 0.05W; Manufacturer Part Number: RC0201FR-07100KL; Alt. Manufacturer Part Number: Any; Manufacturer: Yageo; Substitutes Allowed: YES
R90 = CMP-RES-514-00293-1.1: RES, SMT, 0201, Thick Film, 31.6k, 1%, 0.05W; Alt. Manufacturer: Any; Manufacturer Part Number: RC0201FR-0731K6L; Manufacturer: Yageo; Substitutes Allowed: YES
R114 R115 R121-R123 = CMP-RES-514-00004-1.31: RES, SMT, 0201, Thick Film, 0, 0.05W; Manufacturer: Yageo; Alt. Manufacturer Part Number: Any; Manufacturer Part Number: RC0201JR-070RL; Substitutes Allowed: YES; Tolerance: NA; Value: 0
TP12 TP13 TP15-TP20 = CMP-MSC-522-00070-1.0: MSC, SMT, 1.5mm, Test Pad
U10 U21 = CMP-IC-510-00264-1.1: IC, SMT, VSSOP8, Level Translator, Bidirectional, 2-Bit,  SMT, 1.65V~5.5V, 1A, VFSOP8, 2mm x 2.3mm; Manufacturer: Texas Instruments; Substitutes Allowed: NO; Supply Current: 10uA
U14 = CMP-IC-510-00072-1.5: IC, SMT, SOT23-5, Reg LDO, 2.5~5.5V, Output 3.3V 600mA; Substitutes Allowed: NO; Supply Voltage: 2.5V~5.5V
U15 = CMP-IC-510-00103-1.2: IC, SMT, SC70-5, Single Power Supply Single Buffer GATE CMOS Logic Level Shifter; Subpart Type: Logic ICs; Manufacturer: Texas Instruments; Substitutes Allowed: NO; Supply Current: 8mA; Supply Voltage: 1.6V~5.5V
U22 = CMP-IC-510-00008-1.6: IC, SMT,  TSSOP14, Logic Translator, 1.65V~5.5V; Manufacturer: Texas Instruments; Supply Current: 100mA; Substitutes Allowed: NO
U23 = CMP-IC-510-00320-1.6: IC, SMT, 8-UFBGA, DSBGA, Level Shifter,1.65 V ~ 3.6 V, ,; Alt. Manufacturer Part Number: TCA9406YZPR; Substitutes Allowed: YES; Supply Current: NA

## Sheet CS-DOC-000013317[BL54H20].SchDoc: =BoardTitle +' BL54H20'
size OrCAD C; Organization: Nordic Semiconductor; DocumentNumber: 2; SheetNumber: 3; SheetTotal: 8; CompanyName: Nordic Semiconductor; DocumentSize: A4; SheetName: BL54H20
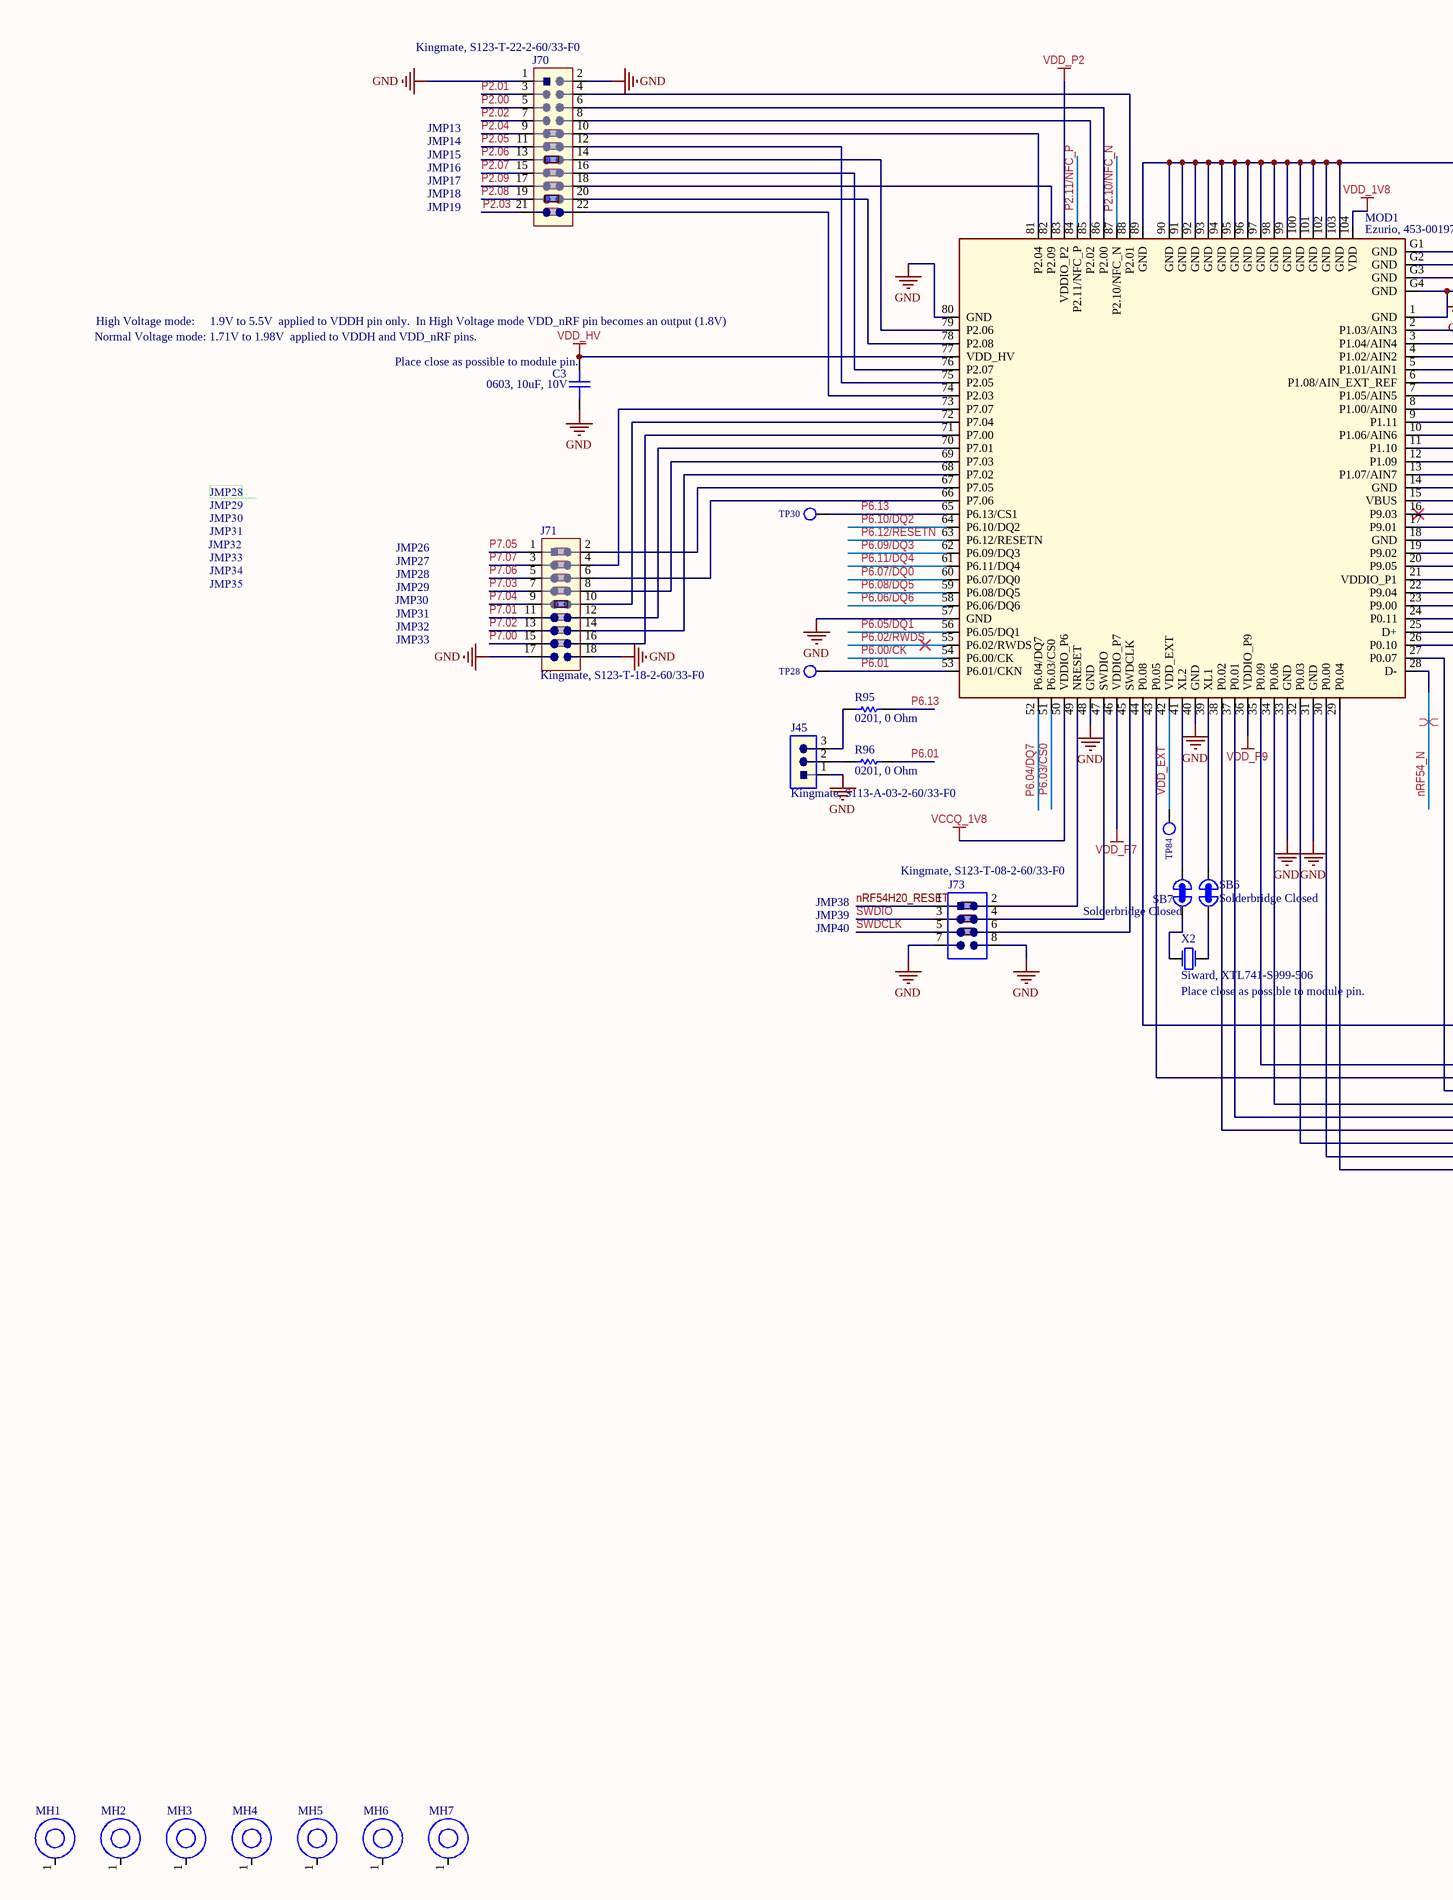
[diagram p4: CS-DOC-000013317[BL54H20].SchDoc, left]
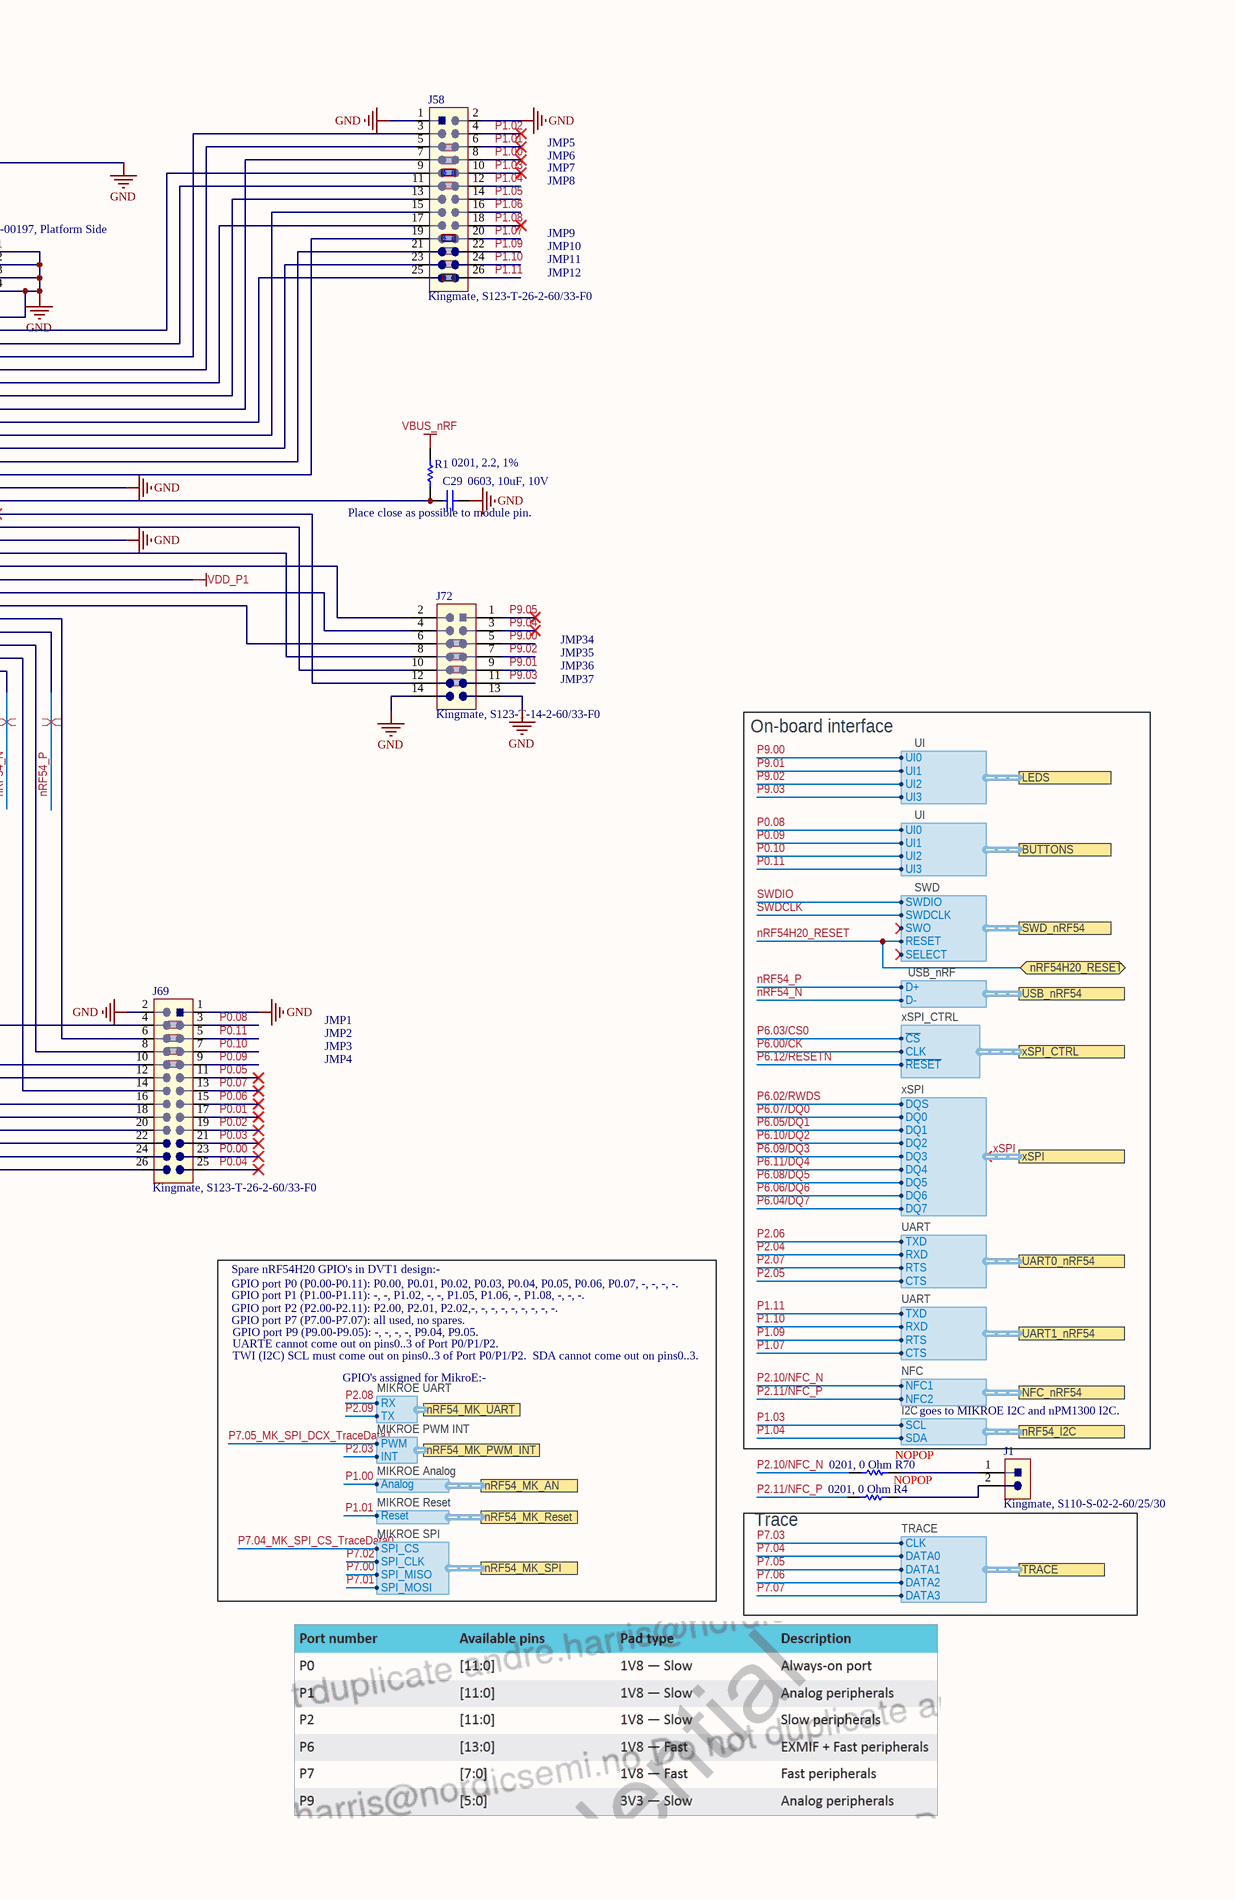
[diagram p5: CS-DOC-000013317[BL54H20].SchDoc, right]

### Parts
C3  0603, 10uF, 10V  [Chip, 0603, RF]
C29  0603, 10uF, 10V  [Chip, 0603, RF]
J1  Kingmate, S110-S-02-2-60/25/30  [2P54MM-1X2, male]
J45  Kingmate, S113-A-03-2-60/33-F0  [2P54MM-1X3, male]
J58  Kingmate, S123-T-26-2-60/33-F0  [2P54MM-2X13Male]
J69  Kingmate, S123-T-26-2-60/33-F0  [2P54MM-2X13Male]
J70  Kingmate, S123-T-22-2-60/33-F0  [2P54MM-2X11 Male]
J71  Kingmate, S123-T-18-2-60/33-F0  [2P54MM-2X9 Male]
J72  Kingmate, S123-T-14-2-60/33-F0  [2P54MM-2X7 Male]
J73  Kingmate, S123-T-08-2-60/33-F0  [2P54MM-2X4 Male]
JMP1  Kingmate, S901D-1-1-E1  [Sullins, QPC02SXGN-RC]  (value not drawn)
JMP2  Kingmate, S901D-1-1-E1  [Sullins, QPC02SXGN-RC]  (value not drawn)
JMP3  Kingmate, S901D-1-1-E1  [Sullins, QPC02SXGN-RC]  (value not drawn)
JMP4  Kingmate, S901D-1-1-E1  [Sullins, QPC02SXGN-RC]  (value not drawn)
JMP5  Kingmate, S901D-1-1-E1  [Sullins, QPC02SXGN-RC]  (value not drawn)
JMP6  Kingmate, S901D-1-1-E1  [Sullins, QPC02SXGN-RC]  (value not drawn)
JMP7  Kingmate, S901D-1-1-E1  [Sullins, QPC02SXGN-RC]  (value not drawn)
JMP8  Kingmate, S901D-1-1-E1  [Sullins, QPC02SXGN-RC]  (value not drawn)
JMP9  Kingmate, S901D-1-1-E1  [Sullins, QPC02SXGN-RC]  (value not drawn)
JMP10  Kingmate, S901D-1-1-E1  [Sullins, QPC02SXGN-RC]  (value not drawn)
JMP11  Kingmate, S901D-1-1-E1  [Sullins, QPC02SXGN-RC]  (value not drawn)
JMP12  Kingmate, S901D-1-1-E1  [Sullins, QPC02SXGN-RC]  (value not drawn)
JMP13  Kingmate, S901D-1-1-E1  [Sullins, QPC02SXGN-RC]  (value not drawn)
JMP14  Kingmate, S901D-1-1-E1  [Sullins, QPC02SXGN-RC]  (value not drawn)
JMP15  Kingmate, S901D-1-1-E1  [Sullins, QPC02SXGN-RC]  (value not drawn)
JMP16  Kingmate, S901D-1-1-E1  [Sullins, QPC02SXGN-RC]  (value not drawn)
JMP17  Kingmate, S901D-1-1-E1  [Sullins, QPC02SXGN-RC]  (value not drawn)
JMP18  Kingmate, S901D-1-1-E1  [Sullins, QPC02SXGN-RC]  (value not drawn)
JMP19  Kingmate, S901D-1-1-E1  [Sullins, QPC02SXGN-RC]  (value not drawn)
JMP26  Kingmate, S901D-1-1-E1  [Sullins, QPC02SXGN-RC]  (value not drawn)
JMP27  Kingmate, S901D-1-1-E1  [Sullins, QPC02SXGN-RC]  (value not drawn)
JMP28  Kingmate, S901D-1-1-E1  [Sullins, QPC02SXGN-RC]  (value not drawn)
JMP29  Kingmate, S901D-1-1-E1  [Sullins, QPC02SXGN-RC]  (value not drawn)
JMP30  Kingmate, S901D-1-1-E1  [Sullins, QPC02SXGN-RC]  (value not drawn)
JMP31  Kingmate, S901D-1-1-E1  [Sullins, QPC02SXGN-RC]  (value not drawn)
JMP32  Kingmate, S901D-1-1-E1  [Sullins, QPC02SXGN-RC]  (value not drawn)
JMP33  Kingmate, S901D-1-1-E1  [Sullins, QPC02SXGN-RC]  (value not drawn)
JMP34  Kingmate, S901D-1-1-E1  [Sullins, QPC02SXGN-RC]  (value not drawn)
JMP35  Kingmate, S901D-1-1-E1  [Sullins, QPC02SXGN-RC]  (value not drawn)
JMP36  Kingmate, S901D-1-1-E1  [Sullins, QPC02SXGN-RC]  (value not drawn)
JMP37  Kingmate, S901D-1-1-E1  [Sullins, QPC02SXGN-RC]  (value not drawn)
JMP38  Kingmate, S901D-1-1-E1  [Sullins, QPC02SXGN-RC]  (value not drawn)
JMP39  Kingmate, S901D-1-1-E1  [Sullins, QPC02SXGN-RC]  (value not drawn)
JMP40  Kingmate, S901D-1-1-E1  [Sullins, QPC02SXGN-RC]  (value not drawn)
MH1  Mounting Hole, Hole 3.2mm, Dia 6mm  [Screw Hole, Hole 3.2mm, Dia 6mm]  (value not drawn)  (no BOM)
MH2  Mounting Hole, Hole 3.2mm, Dia 6mm  [Screw Hole, Hole 3.2mm, Dia 6mm]  (value not drawn)  (no BOM)
MH3  Mounting Hole, Hole 3.2mm, Dia 6mm  [Screw Hole, Hole 3.2mm, Dia 6mm]  (value not drawn)  (no BOM)
MH4  Mounting Hole, Hole 3.2mm, Dia 6mm  [Screw Hole, Hole 3.2mm, Dia 6mm]  (value not drawn)  (no BOM)
MH5  Mounting Hole, Hole 1.524mm, Dia 1.524mm  [Screw Hole, Hole 1.524mm, Dia 1.524mm]  (value not drawn)  (no BOM)
MH6  Mounting Hole, Hole 1.524mm, Dia 1.524mm  [Screw Hole, Hole 1.524mm, Dia 1.524mm]  (value not drawn)  (no BOM)
MH7  Mounting Hole, Hole 1.524mm, Dia 1.524mm  [Screw Hole, Hole 1.524mm, Dia 1.524mm]  (value not drawn)  (no BOM)
MOD1  Ezurio, 453-00197, Platform Side  [Laird, BL54H20 Module, Chip Antenna, Platform Side]
R1  0201, 2.2, 1%  [RES, R0201, Height 0.23mm]
R4  0201, 0 Ohm  [RES, R0201, Height 0.23mm]
R70  0201, 0 Ohm  [RES, R0201, Height 0.23mm]
R95  0201, 0 Ohm  [RES, R0201, Height 0.23mm]
R96  0201, 0 Ohm  [RES, R0201, Height 0.23mm]
SB6  Solderbridge Closed  [Solder Bridge Closed]  (net tie, no BOM)
SB7  Solderbridge Closed  [Solder Bridge Closed]  (net tie, no BOM)
TP28  SMT, 0.7mm, Test Pad  [Test Point, SMT 0.7mm Round]  (value not drawn)  (no BOM)
TP30  SMT, 0.7mm, Test Pad  [Test Point, SMT 0.7mm Round]  (value not drawn)  (no BOM)
TP84  SMT, 0.7mm, Test Pad  [Test Point, SMT 0.7mm Round]  (value not drawn)  (no BOM)
X2  Siward, XTL741-S999-506  [Crystal, 2 pin, 2.0mm x 1.2mm]

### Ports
BUTTONS (harness UI), LEDS (harness UI), NFC_nRF54 (harness NFC), nRF54_I2C (harness I2C), nRF54_MK_AN (harness MIKROE Analog), nRF54_MK_PWM_INT (harness MIKROE PWM INT), nRF54_MK_Reset (harness MIKROE Reset), nRF54_MK_SPI (harness MIKROE SPI), nRF54_MK_UART (harness MIKROE UART), nRF54H20_RESET (bidir), SWD_nRF54 (harness SWD), TRACE (harness TRACE), UART0_nRF54 (harness UART), UART1_nRF54 (harness UART), USB_nRF54 (harness USB_nRF), xSPI (harness xSPI), xSPI_CTRL (harness xSPI_CTRL)

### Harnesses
SWD: SWDIO, SWDCLK, SWO, RESET, SELECT
USB_nRF: D+, D-
TRACE: CLK, DATA0, DATA1, DATA3, DATA2
UI: UI1, UI0, UI2, UI3
I2C: SCL, SDA
MIKROE SPI: SPI_MISO, SPI_MOSI, SPI_CLK, SPI_CS
MIKROE UART: TX, RX
MIKROE PWM INT: PWM, INT
MIKROE Analog: Analog
MIKROE Reset: Reset
xSPI: DQ0, DQ1, DQ2, DQ3, DQ4, DQ5, DQ6, DQ7, DQS
NFC: NFC2, NFC1
UART: RTS, CTS, RXD, TXD
xSPI_CTRL: ~{CS}, CLK, ~{RESET}

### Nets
GND: C3.1 C29.1 J45.1 J58.1 J58.2 J69.1 J69.2 J70.1 J70.2 J71.17 J71.18 J72.13 J72.14 J73.7 J73.8 MOD1.1(GND) MOD1.14(GND) MOD1.18(GND) MOD1.31(GND) MOD1.33(GND) MOD1.40(GND) MOD1.48(GND) MOD1.57(GND) MOD1.80(GND) MOD1.89(GND) MOD1.90(GND) MOD1.91(GND) MOD1.92(GND) MOD1.93(GND) MOD1.94(GND) MOD1.95(GND) MOD1.96(GND) MOD1.97(GND) MOD1.98(GND) MOD1.99(GND) MOD1.100(GND) MOD1.101(GND) MOD1.102(GND) MOD1.103(GND) MOD1.G1(GND) MOD1.G2(GND) MOD1.G3(GND) MOD1.G4(GND)
VBUS_nRF: R1.1
VCCQ_1V8: MOD1.50(VDDIO_P6)
VDD_1V8: MOD1.104(VDD)
VDD_HV: C3.2 MOD1.77(VDD_HV)
VDD_P1: MOD1.21(VDDIO_P1)
VDD_P2: MOD1.83(VDDIO_P2)
VDD_P7: MOD1.46(VDDIO_P7)
VDD_P9: MOD1.36(VDDIO_P9)
nRF54_N: MOD1.28(D-) ; port USB_nRF54.D-
nRF54_P: MOD1.25(D+) ; port USB_nRF54.D+
nRF54H20_RESET: J73.1 ; port nRF54H20_RESET, port SWD_nRF54.RESET
P0.00: J69.23
P0.01: J69.17
P0.02: J69.19
P0.03: J69.21
P0.04: J69.25
P0.05: J69.11
P0.06: J69.15
P0.07: J69.13
P0.08: J69.3 ; port BUTTONS.UI0
P0.09: J69.9 ; port BUTTONS.UI1
P0.10: J69.7 ; port BUTTONS.UI2
P0.11: J69.5 ; port BUTTONS.UI3
P1.00: J58.8 ; port nRF54_MK_AN.Analog
P1.01: J58.6 ; port nRF54_MK_Reset.Reset
P1.02: J58.4
P1.03: J58.10 ; port nRF54_I2C.SCL
P1.04: J58.12 ; port nRF54_I2C.SDA
P1.05: J58.14
P1.06: J58.16
P1.07: J58.20 ; port UART1_nRF54.CTS
P1.08: J58.18
P1.09: J58.22 ; port UART1_nRF54.RTS
P1.10: J58.24 ; port UART1_nRF54.RXD
P1.11: J58.26 ; port UART1_nRF54.TXD
P2.00: J70.5
P2.01: J70.3
P2.02: J70.7
P2.03: J70.21 ; port nRF54_MK_PWM_INT.INT
P2.04: J70.9 ; port UART0_nRF54.RXD
P2.05: J70.11 ; port UART0_nRF54.CTS
P2.06: J70.13 ; port UART0_nRF54.TXD
P2.07: J70.15 ; port UART0_nRF54.RTS
P2.08: J70.19 ; port nRF54_MK_UART.RX
P2.09: J70.17 ; port nRF54_MK_UART.TX
P2.10/NFC_N: MOD1.87(P2.10/NFC_N) R70.1 ; port NFC_nRF54.NFC1
P2.11/NFC_P: MOD1.84(P2.11/NFC_P) R4.1 ; port NFC_nRF54.NFC2
P6.00/CK: MOD1.54(P6.00/CK) ; port xSPI_CTRL.CLK
P6.01: MOD1.53(P6.01/CKN) R96.2 TP28.1
P6.02/RWDS: MOD1.55(P6.02/RWDS) ; port xSPI.DQS
P6.03/CS0: MOD1.51(P6.03/CS0) ; port xSPI_CTRL.~{CS}
P6.04/DQ7: MOD1.52(P6.04/DQ7) ; port xSPI.DQ7
P6.05/DQ1: MOD1.56(P6.05/DQ1) ; port xSPI.DQ1
P6.06/DQ6: MOD1.58(P6.06/DQ6) ; port xSPI.DQ6
P6.07/DQ0: MOD1.60(P6.07/DQ0) ; port xSPI.DQ0
P6.08/DQ5: MOD1.59(P6.08/DQ5) ; port xSPI.DQ5
P6.09/DQ3: MOD1.62(P6.09/DQ3) ; port xSPI.DQ3
P6.10/DQ2: MOD1.64(P6.10/DQ2) ; port xSPI.DQ2
P6.11/DQ4: MOD1.61(P6.11/DQ4) ; port xSPI.DQ4
P6.12/RESETN: MOD1.63(P6.12/RESETN) ; port xSPI_CTRL.~{RESET}
P6.13: MOD1.65(P6.13/CS1) R95.2 TP30.1
P7.00: J71.15 ; port nRF54_MK_SPI.SPI_MISO
P7.01: J71.11 ; port nRF54_MK_SPI.SPI_MOSI
P7.02: J71.13 ; port nRF54_MK_SPI.SPI_CLK
P7.03: J71.7 ; port TRACE.CLK
P7.04: J71.9 ; port TRACE.DATA0
P7.05: J71.1 ; port TRACE.DATA1
P7.06: J71.5 ; port TRACE.DATA2
P7.07: J71.3 ; port TRACE.DATA3
P9.00: J72.5 ; port LEDS.UI0
P9.01: J72.9 ; port LEDS.UI1
P9.02: J72.7 ; port LEDS.UI2
P9.03: J72.11 ; port LEDS.UI3
P9.04: J72.3
P9.05: J72.1
SWDCLK: J73.5 ; port SWD_nRF54.SWDCLK
SWDIO: J73.3 ; port SWD_nRF54.SWDIO
VDD_EXT: MOD1.42(VDD_EXT) TP84.1
NetC29_2: C29.2 MOD1.15(VBUS) R1.2
NetJ1_1: J1.1 R70.2
NetJ1_2: J1.2 R4.2
NetJ45_2: J45.2 R96.1
NetJ45_3: J45.3 R95.1
NetJ58_3: J58.3 MOD1.4(P1.02/AIN2)
NetJ58_5: J58.5 MOD1.5(P1.01/AIN1)
NetJ58_7: J58.7 MOD1.8(P1.00/AIN0)
NetJ58_9: J58.9 MOD1.2(P1.03/AIN3)
NetJ58_11: J58.11 MOD1.3(P1.04/AIN4)
NetJ58_13: J58.13 MOD1.7(P1.05/AIN5)
NetJ58_15: J58.15 MOD1.10(P1.06/AIN6)
NetJ58_17: J58.17 MOD1.6(P1.08/AIN_EXT_REF)
NetJ58_19: J58.19 MOD1.13(P1.07/AIN7)
NetJ58_21: J58.21 MOD1.12(P1.09)
NetJ58_23: J58.23 MOD1.11(P1.10)
NetJ58_25: J58.25 MOD1.9(P1.11)
NetJ69_4: J69.4 MOD1.44(P0.08)
NetJ69_6: J69.6 MOD1.24(P0.11)
NetJ69_8: J69.8 MOD1.26(P0.10)
NetJ69_10: J69.10 MOD1.35(P0.09)
NetJ69_12: J69.12 MOD1.43(P0.05)
NetJ69_14: J69.14 MOD1.27(P0.07)
NetJ69_16: J69.16 MOD1.34(P0.06)
NetJ69_18: J69.18 MOD1.37(P0.01)
NetJ69_20: J69.20 MOD1.38(P0.02)
NetJ69_22: J69.22 MOD1.32(P0.03)
NetJ69_24: J69.24 MOD1.30(P0.00)
NetJ69_26: J69.26 MOD1.29(P0.04)
NetJ70_4: J70.4 MOD1.88(P2.01)
NetJ70_6: J70.6 MOD1.86(P2.00)
NetJ70_8: J70.8 MOD1.85(P2.02)
NetJ70_10: J70.10 MOD1.81(P2.04)
NetJ70_12: J70.12 MOD1.75(P2.05)
NetJ70_14: J70.14 MOD1.79(P2.06)
NetJ70_16: J70.16 MOD1.76(P2.07)
NetJ70_18: J70.18 MOD1.82(P2.09)
NetJ70_20: J70.20 MOD1.78(P2.08)
NetJ70_22: J70.22 MOD1.74(P2.03)
NetJ71_2: J71.2 MOD1.67(P7.05)
NetJ71_4: J71.4 MOD1.73(P7.07)
NetJ71_6: J71.6 MOD1.66(P7.06)
NetJ71_8: J71.8 MOD1.69(P7.03)
NetJ71_10: J71.10 MOD1.72(P7.04)
NetJ71_12: J71.12 MOD1.70(P7.01)
NetJ71_14: J71.14 MOD1.68(P7.02)
NetJ71_16: J71.16 MOD1.71(P7.00)
NetJ72_2: J72.2 MOD1.20(P9.05)
NetJ72_4: J72.4 MOD1.22(P9.04)
NetJ72_6: J72.6 MOD1.23(P9.00)
NetJ72_8: J72.8 MOD1.19(P9.02)
NetJ72_10: J72.10 MOD1.17(P9.01)
NetJ72_12: J72.12 MOD1.16(P9.03)
NetJ73_2: J73.2 MOD1.49(NRESET)
NetJ73_4: J73.4 MOD1.47(SWDIO)
NetJ73_6: J73.6 MOD1.45(SWDCLK)
NetMOD1_39: MOD1.39(XL1) SB6.2
NetMOD1_41: MOD1.41(XL2) SB7.2
NetSB6_1: SB6.1 X2.2(out)
NetSB7_1: SB7.1 X2.1(inp)

Not connected (* = marked no-connect by the designer): MH1 1(PAD); MH2 1(PAD); MH3 1(PAD); MH4 1(PAD); MH5 1(PAD); MH6 1(PAD); MH7 1(PAD)

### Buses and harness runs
harness xSPI = port xSPI

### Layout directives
differential pair; differential pair class nRF54; net class USB: nRF54_N, nRF54_P

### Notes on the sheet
- Normal Voltage mode: 1.71V to 1.98V  applied to VDDH and VDD_nRF pins.
- (near C3) High Voltage mode:     1.9V to 5.5V  applied to VDDH pin only.  In High Voltage mode VDD_nRF pin becomes an output (1.8V)
- (near C3) Place close as possible to module pin.
- (near C29) Place close as possible to module pin.
- On-board interface
- (near X2) Place close as possible to module pin.
- Spare nRF54H20 GPIO's in DVT1 design:-
- GPIO port P2 (P2.00-P2.11): P2.00, P2.01, P2.02,-, -, -, -, -, -, -, -, -.
- GPIO port P0 (P0.00-P0.11): P0.00, P0.01, P0.02, P0.03, P0.04, P0.05, P0.06, P0.07, -, -, -, -.
- GPIO port P1 (P1.00-P1.11): -, -, P1.02, -, -, P1.05, P1.06, -, P1.08, -, -, -.
- GPIO port P7 (P7.00-P7.07): all used, no spares.
- GPIO port P9 (P9.00-P9.05): -, -, -, -, P9.04, P9.05.
- UARTE cannot come out on pins0..3 of Port P0/P1/P2.
- TWI (I2C) SCL must come out on pins0..3 of Port P0/P1/P2.  SDA cannot come out on pins0..3.
- GPIO's assigned for MikroE:-
- (near R70) NOPOP
- goes to MIKROE I2C and nPM1300 I2C.
- Trace
- NOPOP

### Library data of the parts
C3 C29 = CMP-CAP-502-00414-1.2: CAP, SMT, 0603, MLCC, 10uF, 10V, X6S, 10%; Manufacturer Part Number: GRM188C81A106KA73#; Manufacturer: Murata; Substitutes Allowed: NO
J1 = CMP-CON-130-00034-1.8: CON, TH, Header, 2 pin, 2.54mm pitch, Male, Vertical; Substitutes Allowed: NO; Rows: 1; Voltage: 1000V
J45 = CMP-CON-130-00220-1.3: CON, SMT, Header, 1X3 pins, 2.54mm pitch, Male, Vertical; Substitutes Allowed: NO; Rows: 1
J58 J69 = CMP-CON-130-00259-1.1: CON, SMT, Vertical Header, 2X13 pins, 2.54mm pitch, Male, PHY 0.64mm; Rows: 2
J70 = CMP-CON-130-00255-1.1: CON, SMT, Vertical Header, 2X11 pins, 2.54mm pitch, Male, PHY 0.64mm; Rows: 2; Substitutes Allowed: NO
J71 = CMP-CON-130-00256-1.1: CON, SMT, Vertical Header, 2X9 pins, 2.54mm pitch, Male, PHY 0.64mm; Rows: 2; Substitutes Allowed: NO
J72 = CMP-CON-130-00257-1.1: CON, SMT, Vertical Header, 2X7 pins, 2.54mm pitch, Male, PHY 0.64mm; Substitutes Allowed: NO; Rows: 2
J73 = CMP-CON-130-00253-1.0: CON, SMT, Vertical  Header, Male Pin, 2x4, 2.54mm, PHY 0.64mm; Rows: 2; POP Option: NA
JMP1-JMP19 JMP26-JMP40 = CMP-CON-130-00121-1.11: CON, TH, Pin header jumper CAP open type, Pitch 2.54mm,; Alt. Manufacturer Part Number: Any; Rows: 1; Substitutes Allowed: YES
MH1-MH4 = CMP-MSC-522-00015-1.2: MSC, Mounting Hole, Hole 3.2mm, Dia 6mm
MH5-MH7 = CMP-MSC-522-00017-1.1: MSC, Mounting Hole, Hole 1.524mm, Dia 1.524mm
MOD1 = CMP-MOD-453-00095-1.16: MOD, SMT, BL54H20, Chip Antenna; Substitutes Allowed: NO
R1 = CMP-RES-514-00319-1.1: RES, SMT, 0201, Thick Film, 2.2, 1%, 0.05W; Alt. Manufacturer: Any; Manufacturer: Yageo; Manufacturer Part Number: RC0201FR-072R2L; Substitutes Allowed: YES; Value: 2.2
R4 R70 = CMP-RES-514-00004-1.31: as R43 on sheet CS-DOC-000013317[Connectors]
R95 R96 = CMP-RES-514-00004-1.31: as R114 on sheet CS-DOC-000013317[Connectors]
SB6 SB7 = CMP-Misc-522-00004-1.17: MSC, Solderbridge Closed
TP28 TP30 TP84 = CMP-MSC-522-00071-1.0: MSC, SMT, 0.7mm, Test Pad
X2 = CMP-XTL-524-00025-1.1: XTL, SMT, 2 pin, 2.0mm x 1.2mm, 32.768KMHz, 20ppm, 80 kOhm, 9pF; Value: 32.768kHz; ESR: 80 kOhm; Substitutes Allowed: NO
